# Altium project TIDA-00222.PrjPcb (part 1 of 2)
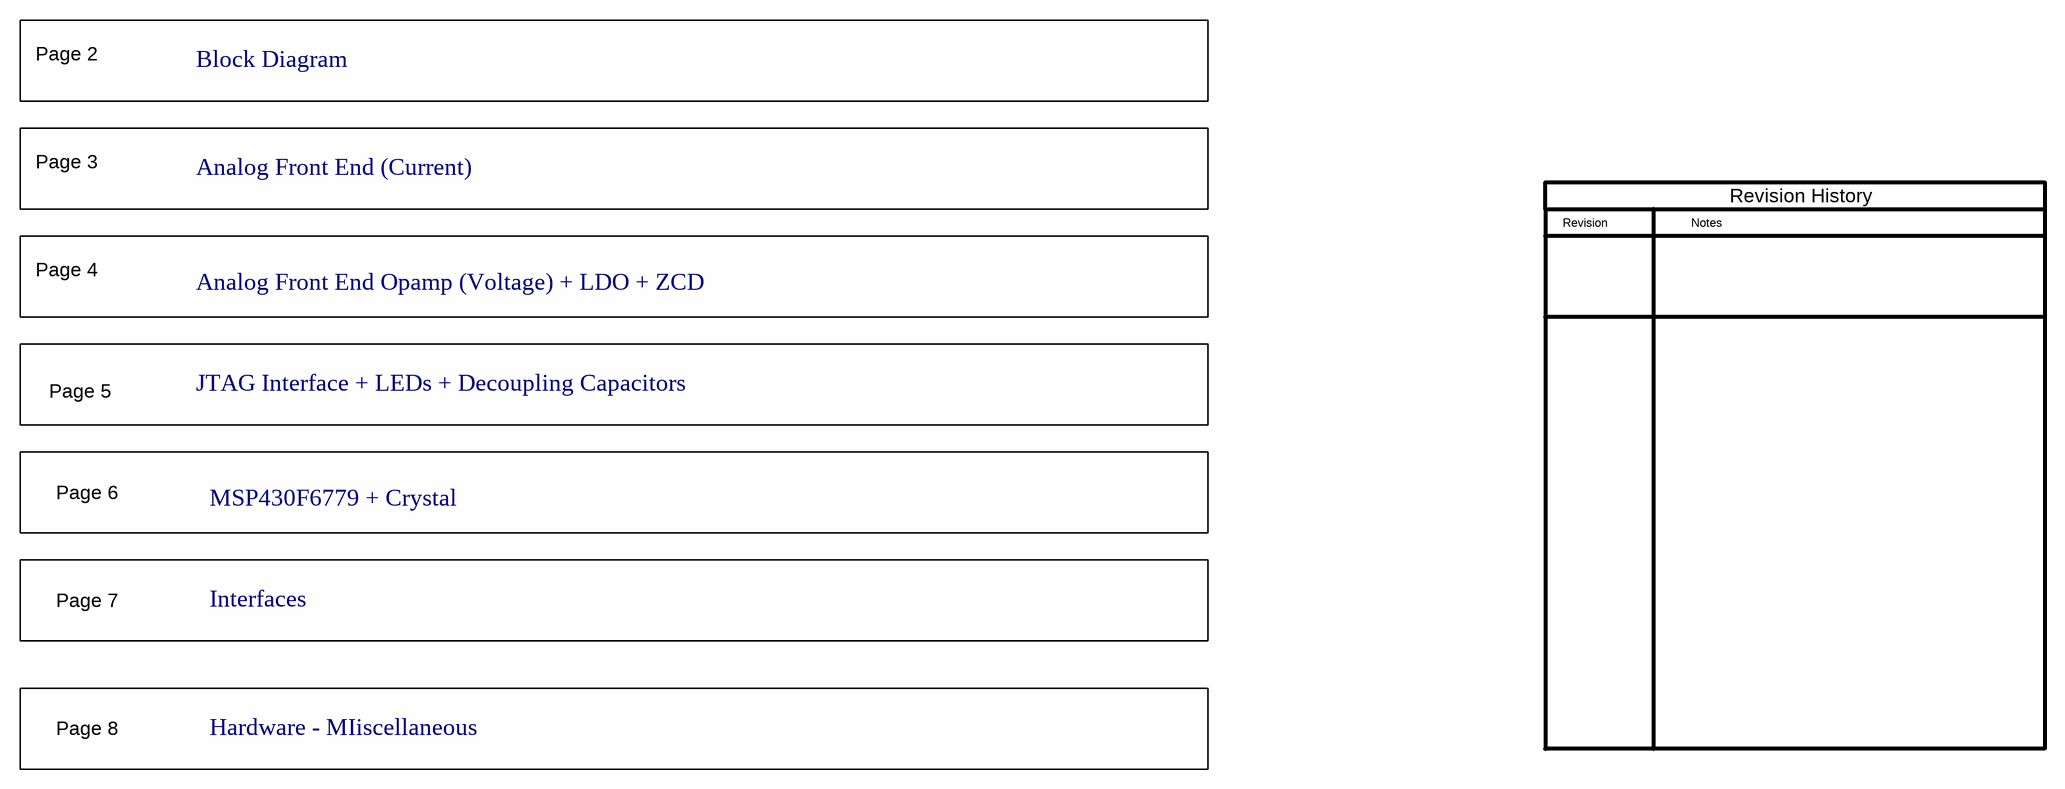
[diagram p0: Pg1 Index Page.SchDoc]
CopyrightYear: 2014; PCB_Rev: E1; PRJ_Customer: Public Release; PRJ_Engineer: Prahlad Supeda; PRJ_Number: TIDA-00222; PRJ_Title: TIDA-0022 - ISE3004; SCH_Rev: E1; TechSupport: http://www.ti.com/support
8 sheets, 217 parts. Net scope: flat (ports and power ports of the same name join across sheets).
Board file: TIDA-00222.PcbDoc
Sheets:
  Pg1 Index Page.SchDoc
  Pg2 Block Diagram.SchDoc
  Pg3.Analog Front End (Current).SchDoc
  Pg4.Analog Front End Opamp (Voltage) + LDO + ZCD.SchDoc
  Pg5.JTAG Interface + LEDs + Decoupling Capacitors.SchDoc
  Pg6.MSP430F6779 + Crystal.SchDoc
  Pg7.Interfaces.SchDoc
  Pg8.HARDWARE - MISCELLANEOUS.SchDoc

## Sheet Pg1 Index Page.SchDoc: Index Page
size 431 x 279 mm; Date: Not shown in title block; ApprovedBy: Not shown in title block; CheckedBy: Not shown in title block; Author: Not shown in title block; CompanyName: Not shown in title block; Engineer: Not shown in title block; Organization: Not shown in title block; Address1: Not shown in title block; Address2: Not shown in title block; Address3: Not shown in title block; Address4: Not shown in title block; DocumentNumber: 1; Revision: Use project parameter SCH_Rev; SheetNumber: 1; SheetTotal: 8; PageSetup: Record=PageOptions|CenterHorizontal=True|CenterVertical=True|PrintScale=1.00|XCorrection=1.00|YCorrection=1.00|PrintKind=0|BorderSize=5000000|LeftOffset=0|BottomOffset=0|Orientation=2|PaperLength=1000|PaperWidth=1000|Scale=100|PaperSource=15|PrintQuality=600|MediaType=1|DitherType=10|PaperKind=Letter|PrintScaleMode=1

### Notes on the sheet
- Page 2
- Block Diagram
- Page 3
- Analog Front End (Current)
- Revision
- Notes
- Revision History
- Page 4
- Analog Front End Opamp (Voltage) + LDO + ZCD
- Page 5
- JTAG Interface + LEDs + Decoupling Capacitors
- Page 6
- MSP430F6779 + Crystal
- Page 7
- Interfaces
- Page 8
- Hardware - MIiscellaneous

## Sheet Pg2 Block Diagram.SchDoc: Block Diagram
size 431 x 279 mm; Date: Not shown in title block; ApprovedBy: Not shown in title block; CheckedBy: Not shown in title block; Author: Not shown in title block; CompanyName: Not shown in title block; Engineer: Not shown in title block; Organization: Not shown in title block; Address1: Not shown in title block; Address2: Not shown in title block; Address3: Not shown in title block; Address4: Not shown in title block; DocumentNumber: 2; Revision: Use project parameter SCH_Rev; SheetNumber: 2; SheetTotal: 8; PageSetup: Record=PageOptions|CenterHorizontal=True|CenterVertical=True|PrintScale=1.00|XCorrection=1.00|YCorrection=1.00|PrintKind=0|BorderSize=5000000|LeftOffset=0|BottomOffset=0|Orientation=2|PaperLength=1000|PaperWidth=1000|Scale=100|PaperSource=15|PrintQuality=600|MediaType=1|DitherType=10|PaperKind=Letter|PrintScaleMode=1
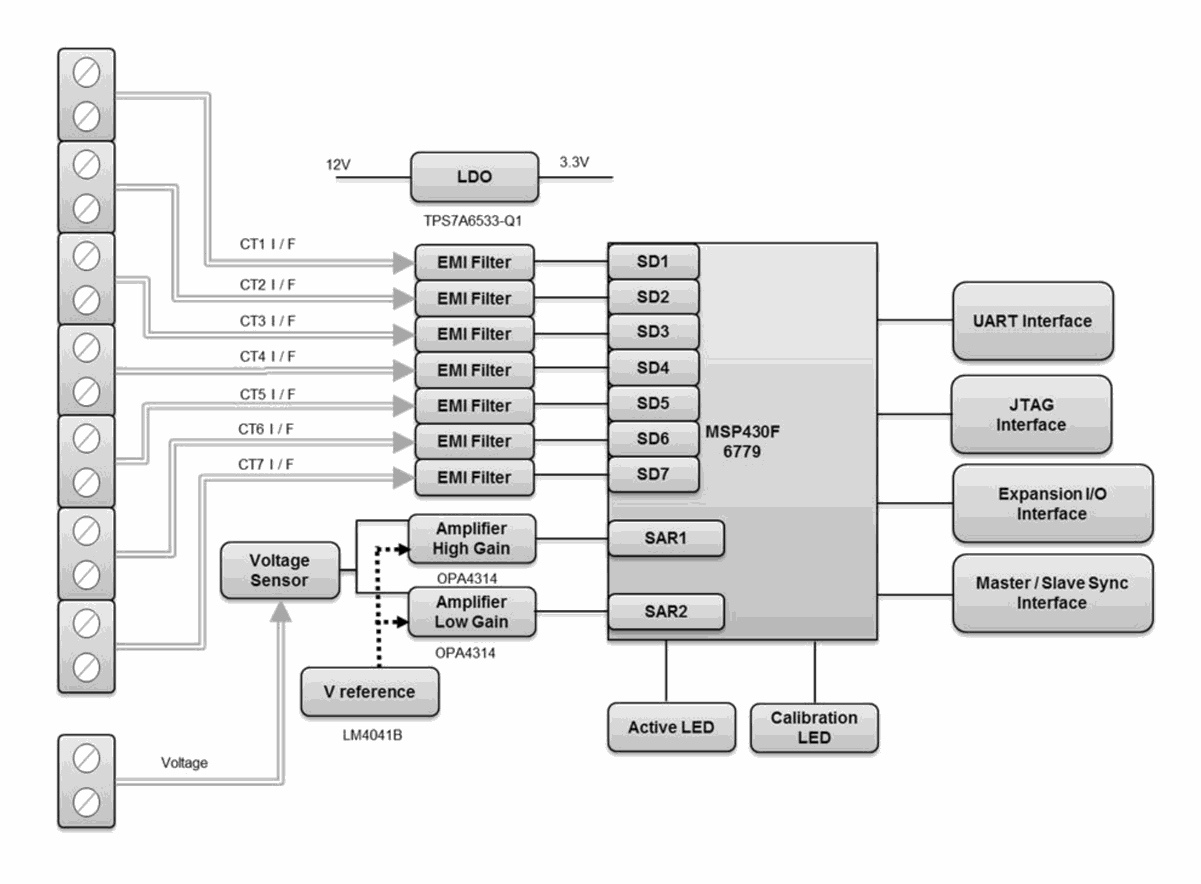
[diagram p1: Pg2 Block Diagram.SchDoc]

## Sheet Pg3.Analog Front End (Current).SchDoc: Analog Front End (Current)
size 431 x 279 mm; Date: Not shown in title block; ApprovedBy: Not shown in title block; CheckedBy: Not shown in title block; Author: Not shown in title block; CompanyName: Not shown in title block; Engineer: Not shown in title block; Organization: Not shown in title block; Address1: Not shown in title block; Address2: Not shown in title block; Address3: Not shown in title block; Address4: Not shown in title block; DocumentNumber: 3; Revision: Use project parameter SCH_Rev; SheetNumber: 3; SheetTotal: 8; PageSetup: Record=PageOptions|CenterHorizontal=True|CenterVertical=True|PrintScale=1.00|XCorrection=1.00|YCorrection=1.00|PrintKind=0|BorderSize=5000000|LeftOffset=0|BottomOffset=0|Orientation=2|PaperLength=1000|PaperWidth=1000|Scale=100|PaperSource=15|PrintQuality=600|MediaType=1|DitherType=10|PaperKind=Letter|PrintScaleMode=1
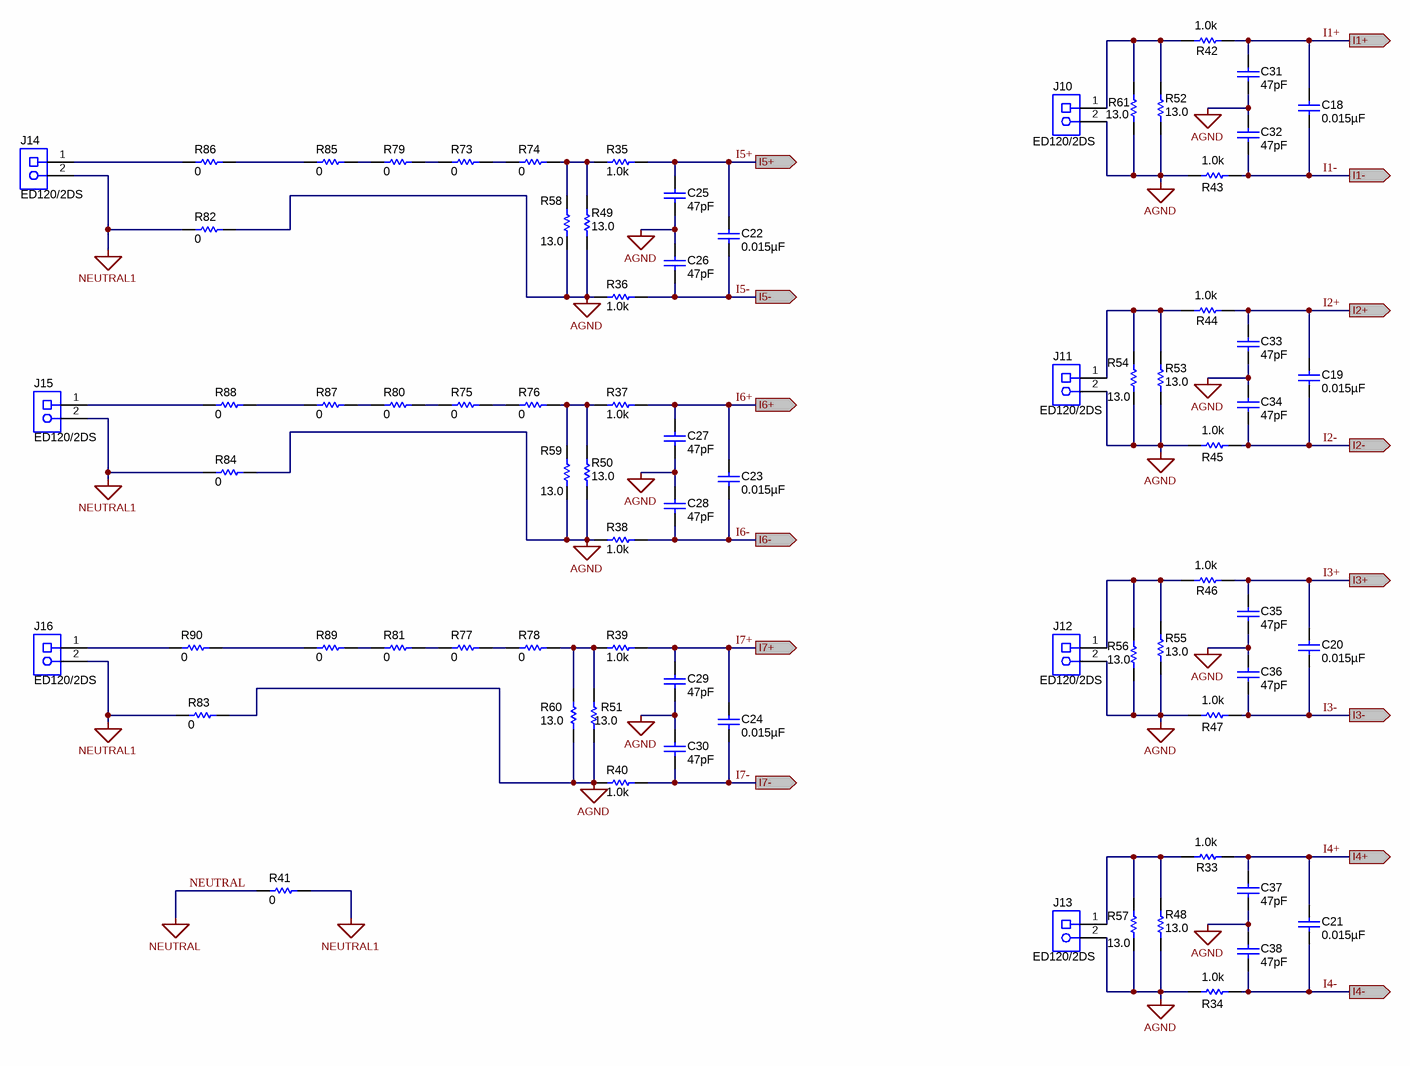
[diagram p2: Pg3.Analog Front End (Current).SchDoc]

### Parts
C18  ValueDisplayed: 0.015µF  [0805_HV]  (hidden comment: 08055C153KAT2A)
C19  ValueDisplayed: 0.015µF  [0805_HV]  (hidden comment: 08055C153KAT2A)
C20  ValueDisplayed: 0.015µF  [0805_HV]  (hidden comment: 08055C153KAT2A)
C21  ValueDisplayed: 0.015µF  [0805_HV]  (hidden comment: 08055C153KAT2A)
C22  ValueDisplayed: 0.015µF  [0805_HV]  (hidden comment: 08055C153KAT2A)
C23  ValueDisplayed: 0.015µF  [0805_HV]  (hidden comment: 08055C153KAT2A)
C24  ValueDisplayed: 0.015µF  [0805_HV]  (hidden comment: 08055C153KAT2A)
C25  ValueDisplayed: 47pF  [0805_HV]  (hidden comment: GRM21A5C2E470JW01D)
C26  ValueDisplayed: 47pF  [0805_HV]  (hidden comment: GRM21A5C2E470JW01D)
C27  ValueDisplayed: 47pF  [0805_HV]  (hidden comment: GRM21A5C2E470JW01D)
C28  ValueDisplayed: 47pF  [0805_HV]  (hidden comment: GRM21A5C2E470JW01D)
C29  ValueDisplayed: 47pF  [0805_HV]  (hidden comment: GRM21A5C2E470JW01D)
C30  ValueDisplayed: 47pF  [0805_HV]  (hidden comment: GRM21A5C2E470JW01D)
C31  ValueDisplayed: 47pF  [0805_HV]  (hidden comment: GRM21A5C2E470JW01D)
C32  ValueDisplayed: 47pF  [0805_HV]  (hidden comment: GRM21A5C2E470JW01D)
C33  ValueDisplayed: 47pF  [0805_HV]  (hidden comment: GRM21A5C2E470JW01D)
C34  ValueDisplayed: 47pF  [0805_HV]  (hidden comment: GRM21A5C2E470JW01D)
C35  ValueDisplayed: 47pF  [0805_HV]  (hidden comment: GRM21A5C2E470JW01D)
C36  ValueDisplayed: 47pF  [0805_HV]  (hidden comment: GRM21A5C2E470JW01D)
C37  ValueDisplayed: 47pF  [0805_HV]  (hidden comment: GRM21A5C2E470JW01D)
C38  ValueDisplayed: 47pF  [0805_HV]  (hidden comment: GRM21A5C2E470JW01D)
J10  ED120/2DS  [CONN_ED120-2DS]
J11  ED120/2DS  [CONN_ED120-2DS]
J12  ED120/2DS  [CONN_ED120-2DS]
J13  ED120/2DS  [CONN_ED120-2DS]
J14  ED120/2DS  [CONN_ED120-2DS]
J15  ED120/2DS  [CONN_ED120-2DS]
J16  ED120/2DS  [CONN_ED120-2DS]
R33  value 1.0k  [0603]  (hidden comment: CRCW06031K00JNEA)
R34  value 1.0k  [0603]  (hidden comment: CRCW06031K00JNEA)
R35  value 1.0k  [0603]  (hidden comment: CRCW06031K00JNEA)
R36  value 1.0k  [0603]  (hidden comment: CRCW06031K00JNEA)
R37  value 1.0k  [0603]  (hidden comment: CRCW06031K00JNEA)
R38  value 1.0k  [0603]  (hidden comment: CRCW06031K00JNEA)
R39  value 1.0k  [0603]  (hidden comment: CRCW06031K00JNEA)
R40  value 1.0k  [0603]  (hidden comment: CRCW06031K00JNEA)
R41  value 0  [0805_HV]  (hidden comment: CRCW08050000Z0EA)
R42  value 1.0k  [0603]  (hidden comment: CRCW06031K00JNEA)
R43  value 1.0k  [0603]  (hidden comment: CRCW06031K00JNEA)
R44  value 1.0k  [0603]  (hidden comment: CRCW06031K00JNEA)
R45  value 1.0k  [0603]  (hidden comment: CRCW06031K00JNEA)
R46  value 1.0k  [0603]  (hidden comment: CRCW06031K00JNEA)
R47  value 1.0k  [0603]  (hidden comment: CRCW06031K00JNEA)
R48  value 13.0  [0805_HV]  (hidden comment: CRCW080513R0FKEA)
R49  value 13.0  [0805_HV]  (hidden comment: CRCW080513R0FKEA)
R50  value 13.0  [0805_HV]  (hidden comment: CRCW080513R0FKEA)
R51  value 13.0  [0805_HV]  (hidden comment: CRCW080513R0FKEA)
R52  value 13.0  [0805_HV]  (hidden comment: CRCW080513R0FKEA)
R53  value 13.0  [0805_HV]  (hidden comment: CRCW080513R0FKEA)
R54  value 13.0  [0805_HV]  (hidden comment: CRCW080513R0FKEA)
R55  value 13.0  [0805_HV]  (hidden comment: CRCW080513R0FKEA)
R56  value 13.0  [0805_HV]  (hidden comment: CRCW080513R0FKEA)
R57  value 13.0  [0805_HV]  (hidden comment: CRCW080513R0FKEA)
R58  value 13.0  [0805_HV]  (hidden comment: CRCW080513R0FKEA)
R59  value 13.0  [0805_HV]  (hidden comment: CRCW080513R0FKEA)
R60  value 13.0  [0805_HV]  (hidden comment: CRCW080513R0FKEA)
R61  value 13.0  [0805_HV]  (hidden comment: CRCW080513R0FKEA)
R73  value 0  [0805_HV]  (hidden comment: CRCW08050000Z0EA)
R74  value 0  [0805_HV]  (hidden comment: CRCW08050000Z0EA)
R75  value 0  [0805_HV]  (hidden comment: CRCW08050000Z0EA)
R76  value 0  [0805_HV]  (hidden comment: CRCW08050000Z0EA)
R77  value 0  [0805_HV]  (hidden comment: CRCW08050000Z0EA)
R78  value 0  [0805_HV]  (hidden comment: CRCW08050000Z0EA)
R79  value 0  [0805_HV]  (hidden comment: CRCW08050000Z0EA)
R80  value 0  [0805_HV]  (hidden comment: CRCW08050000Z0EA)
R81  value 0  [0805_HV]  (hidden comment: CRCW08050000Z0EA)
R82  value 0  [0805_HV]  (hidden comment: CRCW08050000Z0EA)
R83  value 0  [0805_HV]  (hidden comment: CRCW08050000Z0EA)
R84  value 0  [0805_HV]  (hidden comment: CRCW08050000Z0EA)
R85  value 0  [0805_HV]  (hidden comment: CRCW08050000Z0EA)
R86  value 0  [0805_HV]  (hidden comment: CRCW08050000Z0EA)
R87  value 0  [0805_HV]  (hidden comment: CRCW08050000Z0EA)
R88  value 0  [0805_HV]  (hidden comment: CRCW08050000Z0EA)
R89  value 0  [0805_HV]  (hidden comment: CRCW08050000Z0EA)
R90  value 0  [0805_HV]  (hidden comment: CRCW08050000Z0EA)

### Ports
I1+ (out), I1- (out), I2+ (out), I2- (out), I3+ (out), I3- (out), I4+ (out), I4- (out), I5+ (out), I5- (out), I6+ (out), I6- (out), I7+ (out), I7- (out)

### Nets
AGND: C25.2 C26.1 C27.2 C28.1 C29.2 C30.1 C31.2 C32.1 C33.2 C34.1 C35.2 C36.1 C37.2 C38.1 J10.2 J11.2 J12.2 J13.2 R34.2 R36.2 R38.2 R40.2 R43.2 R45.2 R47.2 R48.1 R49.2 R50.2 R51.1 R52.1 R53.1 R54.1 R55.1 R56.1 R57.1 R58.1 R59.1 R60.2 R61.1 R82.2 R83.2 R84.2
NEUTRAL: R41.1
NEUTRAL1: J14.2 J15.2 J16.2 R41.2 R82.1 R83.1 R84.1
I1+: C18.1 C31.1 R42.1 ; port I1+
I1-: C18.2 C32.2 R43.1 ; port I1-
I2+: C19.1 C33.1 R44.1 ; port I2+
I2-: C19.2 C34.2 R45.1 ; port I2-
I3+: C20.1 C35.1 R46.1 ; port I3+
I3-: C20.2 C36.2 R47.1 ; port I3-
I4+: C21.1 C37.1 R33.1 ; port I4+
I4-: C21.2 C38.2 R34.1 ; port I4-
I5+: C22.1 C25.1 R35.1 ; port I5+
I5-: C22.2 C26.2 R36.1 ; port I5-
I6+: C23.1 C27.1 R37.1 ; port I6+
I6-: C23.2 C28.2 R38.1 ; port I6-
I7+: C24.1 C29.1 R39.1 ; port I7+
I7-: C24.2 C30.2 R40.1 ; port I7-
NetJ10_1: J10.1 R42.2 R52.2 R61.2
NetJ11_1: J11.1 R44.2 R53.2 R54.2
NetJ12_1: J12.1 R46.2 R55.2 R56.2
NetJ13_1: J13.1 R33.2 R48.2 R57.2
NetJ14_1: J14.1 R86.1
NetJ15_1: J15.1 R88.1
NetJ16_1: J16.1 R90.1
NetR35_2: R35.2 R49.1 R58.2 R74.2
NetR37_2: R37.2 R50.1 R59.2 R76.2
NetR39_2: R39.2 R51.2 R60.1 R78.2
NetR73_1: R73.1 R79.2
NetR73_2: R73.2 R74.1
NetR75_1: R75.1 R80.2
NetR75_2: R75.2 R76.1
NetR77_1: R77.1 R81.2
NetR77_2: R77.2 R78.1
NetR79_1: R79.1 R85.2
NetR80_1: R80.1 R87.2
NetR81_1: R81.1 R89.2
NetR85_1: R85.1 R86.2
NetR87_1: R87.1 R88.2
NetR89_1: R89.1 R90.2

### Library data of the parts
C18-C24 = 08055C153KAT2A: CAP, CERM, 0.015uF, 50V, +/-10%, X7R, 0805; Manufacturer: AVX; Polarized: N; CompType: Capacitor; U/M: EA; Cap_F: 0.000000015; Tolerance_%: 10; ESR_Ohm: 0.063; Value1: 0.063 ohm; VDC_V: 50; TaMin_C: -55; TaMax_C: 125; Cap_Case: 0805
C25-C38 = GRM21A5C2E470JW01D: CAP, CERM, 47pF, 500V, +/-5%, C0G/NP0, 0805; Manufacturer: MuRata; Polarized: N; CompType: Capacitor; U/M: EA; Cap_F: 0.000000000047; Tolerance_%: 5; Value1: Unknown; VDC_V: 250; Value2: 250V; TaMin_C: -55; TaMax_C: 125; Cap_Case: 0805
J10-J16 = ED120/2DS: TERMINAL BLOCK 5.08MM VERT 2POS, TH; Manufacturer: On-Shore Technology; SymbolCreator: a0412235; U/M: EA
R33-R40 R42-R47 = RC0603JR-071KL: RES, 1.0k ohm, 5%, 0.1W, 0603; Manufacturer: Vishay-Dale; CompType: Resistor; Res_ohm: 1000; Value_Code: 1k00; Tolerance_%: 5; Power_W: 0.1; VDC_V: 50; TempCo: 100 ppm/C; EIA_Code: E24; U/M: EA
R41 R73-R90 = CRCW0805330KJNEA: RES, 0 ohm, 5%, 0.125W, 0805; Manufacturer: Vishay-Dale; CompType: Resistor; Tolerance_%: 5; Power_W: 0.125; VDC_V: 150; TempCo: 200 ppm/C; EIA_Code: E24; U/M: EA
R48-R61 = CRCW080513R0FKEA: RES, 13.0 ohm, 1%, 0.125W, 0805; Manufacturer: Vishay-Dale; CompType: Resistor; Res_ohm: 13; Value_Code: 13R0; Tolerance_%: 1; Power_W: 0.125; VDC_V: 150; TempCo: 100 ppm/C; EIA_Code: E96; U/M: EA

## Sheet Pg4.Analog Front End Opamp (Voltage) + LDO + ZCD.SchDoc: Analog Front End Opamp (Voltage) + LDO + ZCD
size 431 x 279 mm; Date: Not shown in title block; ApprovedBy: Not shown in title block; CheckedBy: Not shown in title block; Author: Not shown in title block; CompanyName: Not shown in title block; Engineer: Not shown in title block; Organization: Not shown in title block; Address1: Not shown in title block; Address2: Not shown in title block; Address3: Not shown in title block; Address4: Not shown in title block; DocumentNumber: 4; Revision: Use project parameter SCH_Rev; SheetNumber: 4; SheetTotal: 8; PageSetup: Record=PageOptions|CenterHorizontal=True|CenterVertical=True|PrintScale=1.00|XCorrection=1.00|YCorrection=1.00|PrintKind=0|BorderSize=5000000|LeftOffset=0|BottomOffset=0|Orientation=2|PaperLength=1000|PaperWidth=1000|Scale=100|PaperSource=15|PrintQuality=600|MediaType=1|DitherType=10|PaperKind=Letter|PrintScaleMode=1
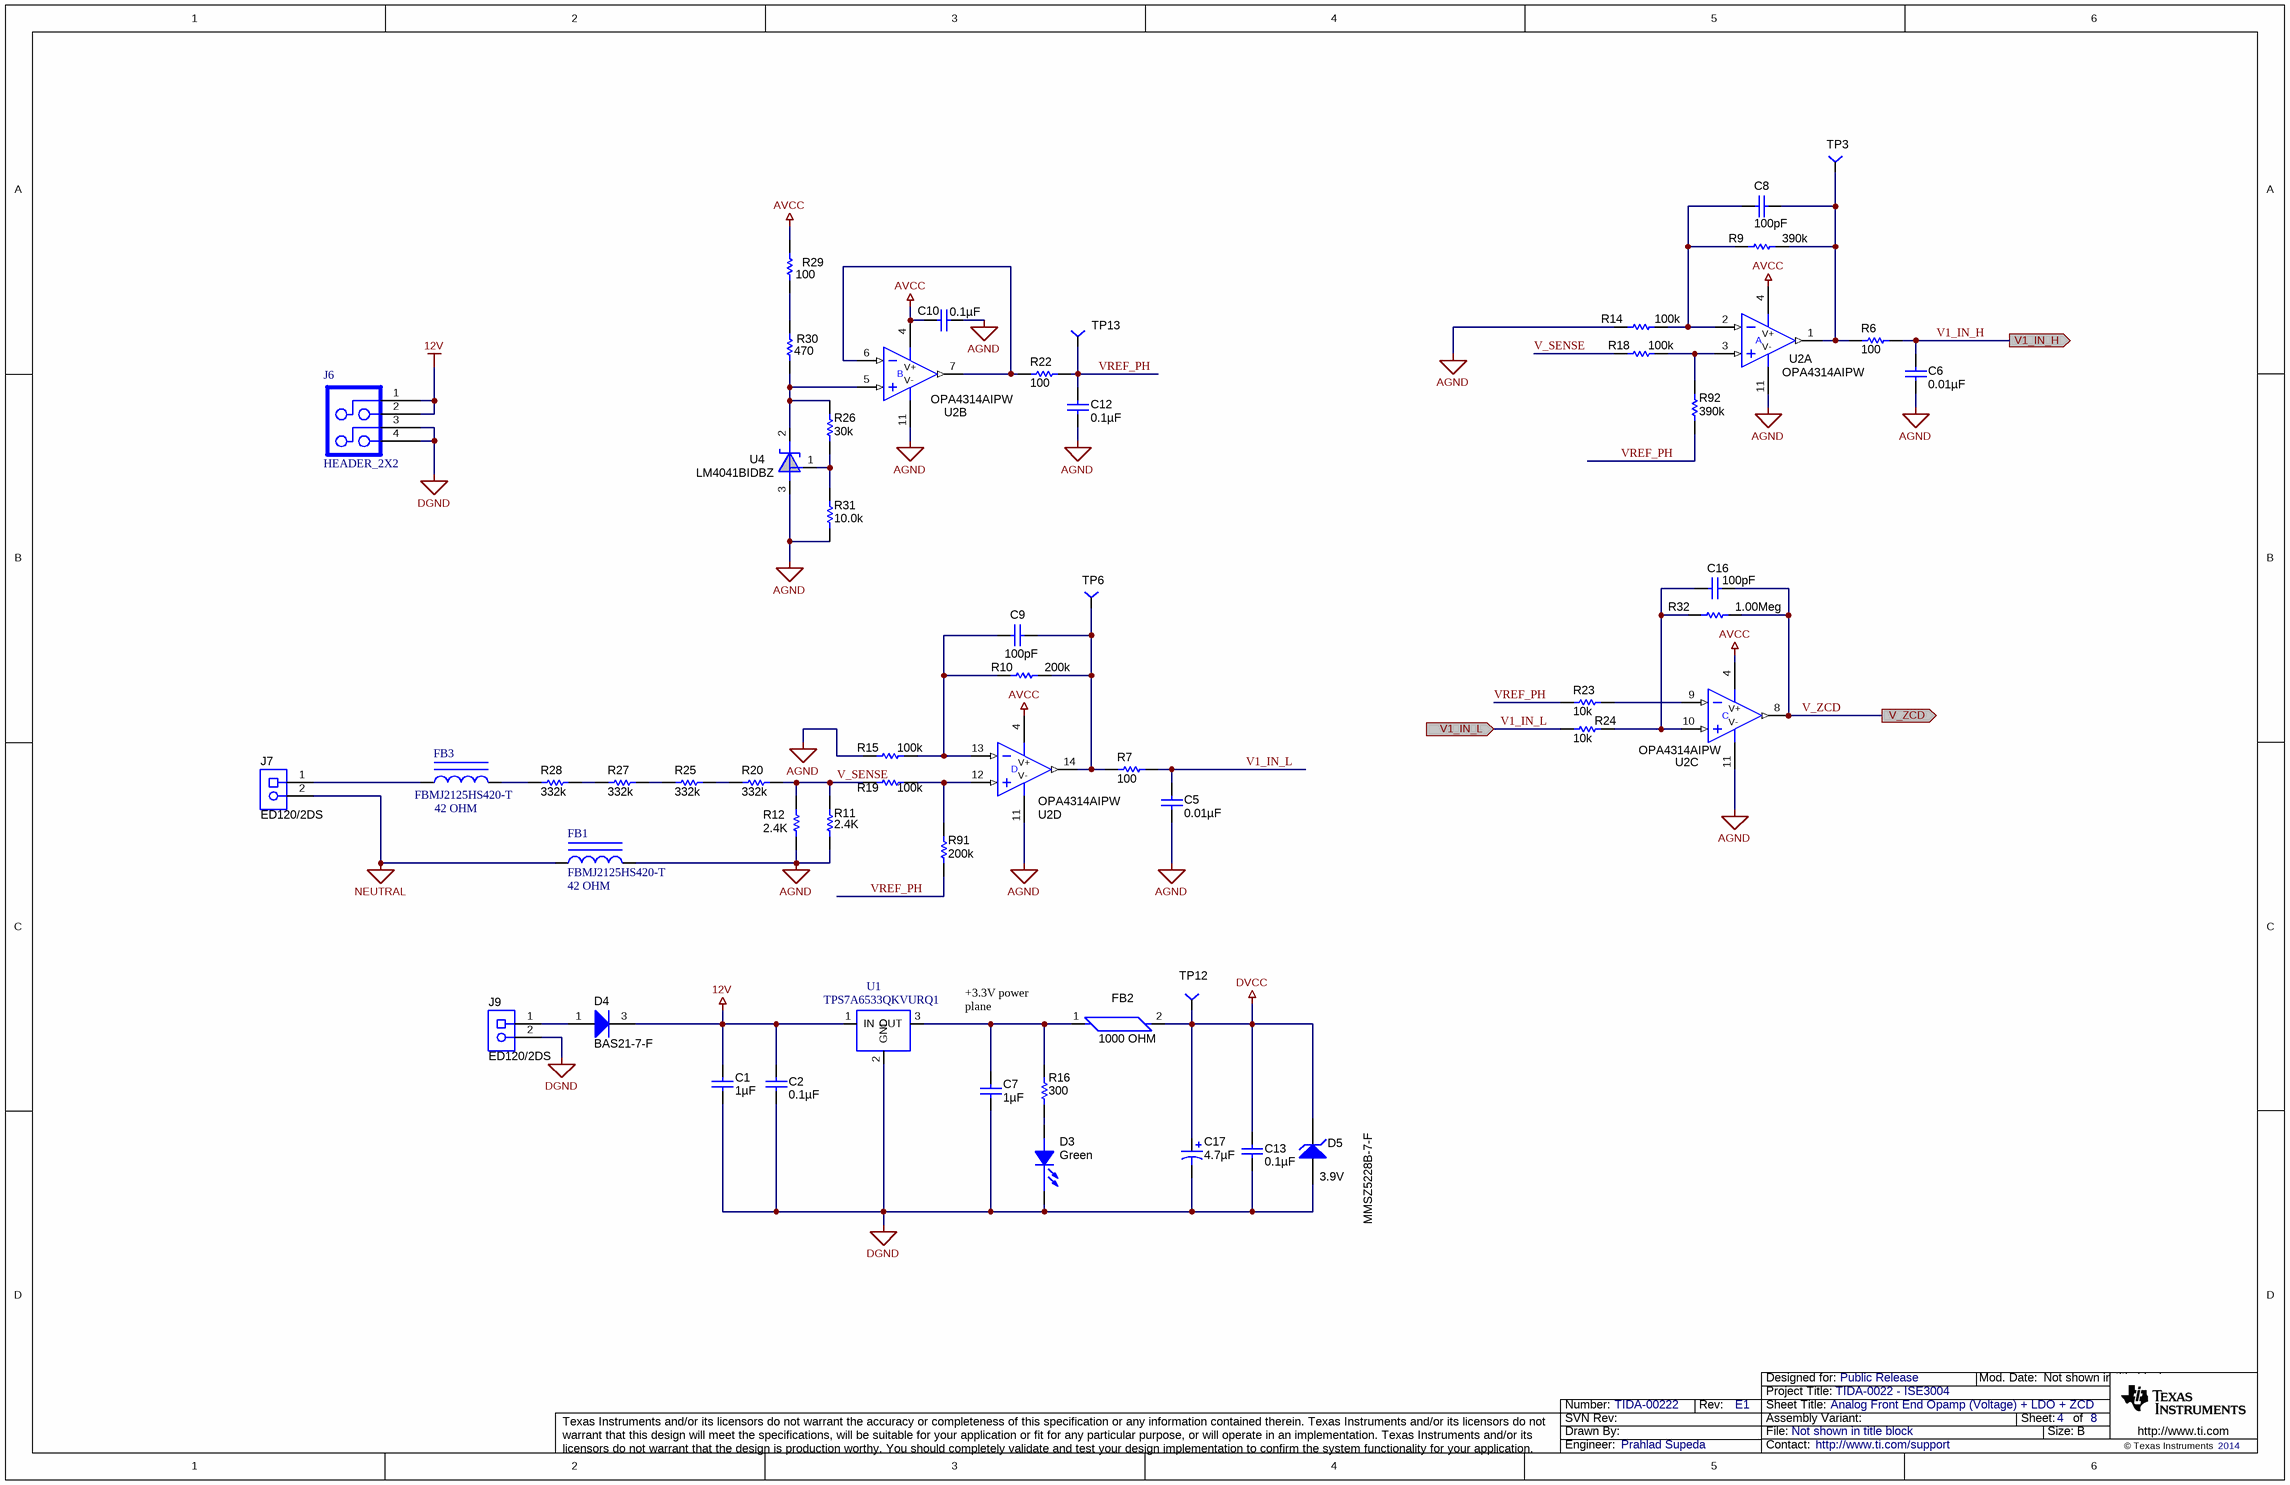
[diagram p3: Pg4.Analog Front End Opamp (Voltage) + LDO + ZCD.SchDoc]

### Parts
C1  ValueDisplayed: 1µF  [0603]  (hidden comment: C1608X7R1C105K)
C2  ValueDisplayed: 0.1µF  [0603]  (hidden comment: C0603C104K5RACTU)
C5  ValueDisplayed: 0.01µF  [0603]  (hidden comment: C1608C0G1E103J)
C6  ValueDisplayed: 0.01µF  [0603]  (hidden comment: C1608C0G1E103J)
C7  ValueDisplayed: 1µF  [0603]  (hidden comment: C1608X7R1C105K)
C8  ValueDisplayed: 100pF  [0603]  (hidden comment: 06035A101FAT2A)
C9  ValueDisplayed: 100pF  [0603]  (hidden comment: 06035A101FAT2A)
C10  ValueDisplayed: 0.1µF  [0603]  (hidden comment: 06033C104JAT2A)
C12  ValueDisplayed: 0.1µF  [0603]  (hidden comment: 06033C104JAT2A)
C13  ValueDisplayed: 0.1µF  [0603]  (hidden comment: C0603C104K5RACTU)
C16  ValueDisplayed: 100pF  [0603]  (hidden comment: 06035A101FAT2A)
C17  ValueDisplayed: 4.7µF  [6032-28]  (hidden comment: 293D475X9035C2TE3)
D3  value Green  [LED0603AA]  (hidden comment: LED_LG L29K-G2J1-24-Z)
D4  BAS21-7-F  [SOT-23]
D5  MMSZ5228B-7-F  value 3.9V  [sod-123]
FB1  FBMJ2125HS420-T  value 42 OHM  [0805_hv]
FB2  1000 OHM  [0603]
FB3  FBMJ2125HS420-T  value 42 OHM  [0805_hv]
J6  HEADER_2X2  [HDR_2X2]
J7  ED120/2DS  [CONN_ED120-2DS]
J9  ED120/2DS  [CONN_ED120-2DS]
R6  value 100  [0603]  (hidden comment: CRCW0603100RFKEA)
R7  value 100  [0603]  (hidden comment: CRCW0603100RFKEA)
R9  value 390k  [0603]  (hidden comment: CRCW0603390KFKEA)
R10  value 200k  [0603]  (hidden comment: CRCW0603200KFKEA)
R11  value 2.4K  [0805_hv]  (hidden comment: CRCW08052K40FKEA)
R12  value 2.4K  [0805_hv]  (hidden comment: CRCW08052K40FKEA)
R14  value 100k  [0603]  (hidden comment: CRCW0603100KFKEA)
R15  value 100k  [0603]  (hidden comment: CRCW0603100KFKEA)
R16  value 300  [0603]  (hidden comment: CRCW0603300RJNEA)
R18  value 100k  [0603]  (hidden comment: CRCW0603100KFKEA)
R19  value 100k  [0603]  (hidden comment: CRCW0603100KFKEA)
R20  value 332k  [0805_HV]  (hidden comment: CRCW0805332KFKEA)
R22  value 100  [0603]  (hidden comment: CRCW0603100RFKEA)
R23  value 10k  [0603]  (hidden comment: CRCW060310K0JNEA)
R24  value 10k  [0603]  (hidden comment: CRCW060310K0JNEA)
R25  value 332k  [0805_HV]  (hidden comment: CRCW0805332KFKEA)
R26  value 30k  [0603]  (hidden comment: CRCW060330K0JNEA)
R27  value 332k  [0805_HV]  (hidden comment: CRCW0805332KFKEA)
R28  value 332k  [0805_HV]  (hidden comment: CRCW0805332KFKEA)
R29  value 100  [0603]  (hidden comment: CRCW0603100RFKEA)
R30  value 470  [0603]  (hidden comment: CRCW0603470RJNEA)
R31  value 10.0k  [0603]  (hidden comment: CRCW060310K0FKEA)
R32  value 1.00Meg  [0603]  (hidden comment: CRCW06031M00FKEA)
R91  value 200k  [0603]  (hidden comment: CRCW0603200KFKEA)
R92  value 390k  [0603]  (hidden comment: CRCW0603390KFKEA)
TP3  TP-040_RND  [TP-040_RND]  (value not drawn)
TP6  TP-040_RND  [TP-040_RND]  (value not drawn)
TP12  TP-040_RND  [TP-040_RND]  (value not drawn)
TP13  TP-040_RND  [TP-040_RND]  (value not drawn)
U1  TPS7A6533QKVURQ1  [KVU_1]
U2  OPA4314AIPW  [PW0014A_N]  (parts A,B,C,D of 4)
U4  LM4041BIDBZ  [SOT-23]

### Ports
V1_IN_H, V1_IN_L, V_ZCD

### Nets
12V: C1.1 C2.1 D4.3(K) J6.1 J6.2 U1.1(IN)
AGND: C5.1 C6.1 C10.1 C12.1 FB1.2 R11.2 R12.2 R14.2 R15.2 R31.1 U2.11(V-) U4.3(A)
AVCC: C10.2 R29.1 U2.4(V+)
DGND: C1.2 C2.2 C7.2 C13.2 C17.2(-) D3.1(C) D5.2(A) J6.3 J6.4 J9.2 U1.2(GND)
DVCC: C13.1 C17.1(+) D5.1(K) FB2.2 TP12.1
NEUTRAL: FB1.1 J7.2
V1_IN_H: C6.2 R6.2 ; port V1_IN_H
V1_IN_L: C5.2 R7.2 R24.2 ; port V1_IN_L
V_SENSE: R11.1 R12.1 R18.2 R19.2 R20.1
V_ZCD: C16.1 R32.2 U2.8(OUT) ; port V_ZCD
VREF_PH: C12.2 R22.2 R23.2 R91.1 R92.2 TP13.1
NetC7_1: C7.1 FB2.1 R16.2 U1.3(OUT)
NetC8_1: C8.1 R6.1 R9.1 TP3.1 U2.1(OUT)
NetC8_2: C8.2 R9.2 R14.1 U2.2(IN-)
NetC9_1: C9.1 R7.1 R10.1 TP6.1 U2.14(OUT)
NetC9_2: C9.2 R10.2 R15.1 U2.13(IN-)
NetC16_2: C16.2 R24.1 R32.1 U2.10(IN+)
NetD3_2: D3.2(A) R16.1
NetD4_1: D4.1(A) J9.1
NetFB3_1: FB3.1 J7.1
NetFB3_2: FB3.2 R28.2
NetR18_1: R18.1 R92.1 U2.3(IN+)
NetR19_1: R19.1 R91.2 U2.12(IN+)
NetR20_2: R20.2 R25.1
NetR22_1: R22.1 U2.6(IN-) U2.7(OUT)
NetR23_1: R23.1 U2.9(IN-)
NetR25_2: R25.2 R27.1
NetR26_1: R26.1 R31.2 U4.1(FB)
NetR26_2: R26.2 R30.1 U2.5(IN+) U4.2(C)
NetR27_2: R27.2 R28.1
NetR29_2: R29.2 R30.2

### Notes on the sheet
- (near FB2) +3.3V power
  plane

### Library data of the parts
C1 C7 = C1608X7R1C105K: CAP, CERM, 1uF, 16V, +/-10%, X7R, 0603; Manufacturer: TDK; Polarized: N; CompType: Capacitor; U/M: EA; Cap_F: 0.000001; Tolerance_%: 10; ESR_Ohm: 0.0057; Value1: 0.0057 ohm; VDC_V: 16; TaMin_C: -55; TaMax_C: 125
C2 C13 = C0603C104K5RACTU: CAP, CERM, 0.1uF, 50V, +/-10%, X7R, 0603; Manufacturer: Kemet; Polarized: N; CompType: Capacitor; U/M: EA; Cap_F: 0.0000001; Tolerance_%: 10; Value1: Unknown; VDC_V: 50; TaMin_C: -55; TaMax_C: 125
C5 C6 = C1608C0G1E103J: CAP, CERM, 0.01uF, 25V, +/-5%, C0G/NP0, 0603; Manufacturer: TDK; Polarized: N; CompType: Capacitor; U/M: EA; Cap_F: 0.00000001; Tolerance_%: 5; Value1: Unknown; VDC_V: 25; TaMin_C: -55; TaMax_C: 125
C8 C9 C16 = 06035A101FAT2A: CAP, CERM, 100pF, 50V, +/-1%, C0G/NP0, 0603; Manufacturer: AVX; Polarized: N; CompType: Capacitor; U/M: EA; Cap_F: 0.0000000001; Tolerance_%: 1; Value1: Unknown; VDC_V: 50; TaMin_C: -55; TaMax_C: 125
C10 C12 = 06033C104JAT2A: CAP, CERM, 0.1uF, 25V, +/-5%, X7R, 0603; Manufacturer: AVX; Polarized: N; CompType: Capacitor; U/M: EA; Cap_F: 0.0000001; Tolerance_%: 5; ESR_Ohm: 0.05; Value1: 0.05 ohm; VDC_V: 25; TaMin_C: -55; TaMax_C: 125
C17 = 293D475X9035C2TE3: CAP, TA, 4.7uF, 35V, +/-10%, 1.9 ohm, SMD; Manufacturer: Vishay-Sprague; Polarized: Y; CompType: Capacitor; U/M: EA; Cap_F: 0.0000047; Tolerance_%: 10; Value1: 1.9 ohm; VDC_V: 35; ESR_Ohm: 1.9; IRMS_A: 0.24; TaMin_C: -55; TaMax_C: 125; Cap_Case: C
D3 = LED_LG L29K-G2J1-24-Z: LED SmartLED Green 570NM; Manufacturer: OSRAM; SymbolCreator: x0120606
D4 = BAS21-7-F: Diode, Switching, 200V, 0.2A, SOT-23; Manufacturer: Diodes Inc.; U/M: EA; Vf_V: 1.25; Value2: 1.25V; Io_A: 0.2; Vr_V: 200; TJmax_C: 150; RJC_CperW: 500
D5 = 1SMB5915BT3G: DIODE ZENER 3.9V 500MW SOD123; Manufacturer: Diodes Incorporated; U/M: EA; Power_W: 0.55; Vz_V: 3.9; Value1: 0.55W; RJA_CperW: 226
FB1 FB3 = FBMJ2125HS420-T: FERRITE BEAD, 42 OHM, 4 A, DCR0.008 OHM, SMT-0805; Manufacturer: TAIYO YUDEN; SymbolCreator: x0199378
FB2 = MMZ1608B102C: FERRITE CHIP 1000 OHM 300MA 0603; Manufacturer: TDK Corporation; CompType: Ferrite Bead
J6 = HEADER_2X2: Header, 2x2-pin, 100mil spacing; Manufacturer: FCI; PartNumber: 67997-404HLF; area: 40000; Value: PEC02DAAN
J7 J9 = ED120/2DS: as J10 on sheet Pg3.Analog Front End (Current)
R6 R7 R22 R29 = CRCW0603100RFKEA: RES, 100 ohm, 1%, 0.1W, 0603; Manufacturer: Vishay-Dale; CompType: Resistor; Value_Code: 100R; Tolerance_%: 1; Power_W: 0.1; VDC_V: 75; TempCo: 100 ppm/C; EIA_Code: E96; U/M: EA
R9 R92 = RC0603FR-0739KL: RES 390K OHM 1/10W 1% 0603 SMD; Manufacturer: Vishay Dale; CompType: Resistor; Tolerance_%: 1; Value2: 0.1W; TempCo: 100 ppm/C; U/M: EA
R10 R91 = CRCW0603200KFKEA: RES, 200k ohm, 1%, 0.1W, 0603; Manufacturer: Vishay-Dale; CompType: Resistor; Res_ohm: 200000; Tolerance_%: 1; Power_W: 0.1; VDC_V: 75; TempCo: 100 ppm/C; EIA_Code: E96; U/M: EA
R11 R12 = CRCW120610K0FKEA: RES 2.40K OHM 1/8W 1% 0805 SMD; Manufacturer: Vishay-Dale; CompType: Resistor; Tolerance_%: 1; Power_W: 0.125W; TempCo: 100 ppm/C; U/M: EA
R14 R15 R18 R19 = CRCW0603100KFKEA: RES, 100k ohm, 1%, 0.1W, 0603; Manufacturer: Vishay-Dale; CompType: Resistor; Res_ohm: 100000; Tolerance_%: 1; Power_W: 0.1; VDC_V: 75; TempCo: 100 ppm/C; EIA_Code: E96; U/M: EA
R16 = CRCW0603300RJNEA: RES, 300 ohm, 5%, 0.1W, 0603; Manufacturer: Vishay-Dale; CompType: Resistor; Value_Code: 300R; Tolerance_%: 5; Power_W: 0.1; VDC_V: 75; TempCo: 200 ppm/C; EIA_Code: E24; U/M: EA
R20 R25 R27 R28 = CRCW0805332KFKEA: RES, 332k ohm, 1%, 0.125W, 0805; Manufacturer: Vishay-Dale; CompType: Resistor; Res_ohm: 332000; Tolerance_%: 1; Power_W: 0.125; VDC_V: 150; TempCo: 100 ppm/C; EIA_Code: E96; U/M: EA
R23 R24 = RNCF0603TKY10K0: RES 10K OHM 1/10W 5% 0603 SMD; Manufacturer: Vishay-Dale; CompType: Resistor; Res_ohm: 10000; Value_Code: 10k0; Tolerance_%: 0.01; Value1: 0.01%; Power_W: 0.063; Value2: 0.063W; VDC_V: 50; TempCo: 5 ppm/C; U/M: EA
R26 = CRCW060330K0JNEA: RES, 30k ohm, 5%, 0.1W, 0603; Manufacturer: Vishay-Dale; CompType: Resistor; Res_ohm: 30000; Value_Code: 30k0; Tolerance_%: 5; Power_W: 0.1; VDC_V: 75; TempCo: 200 ppm/C; EIA_Code: E24; U/M: EA
R30 = CRCW0603470RJNEA: RES, 470 ohm, 5%, 0.1W, 0603; Manufacturer: Vishay-Dale; CompType: Resistor; Value_Code: 470R; Tolerance_%: 5; Power_W: 0.1; VDC_V: 75; TempCo: 200 ppm/C; EIA_Code: E24; U/M: EA
R31 = CRCW060310K0FKEA: RES, 10.0k ohm, 1%, 0.1W, 0603; Manufacturer: Vishay-Dale; CompType: Resistor; Res_ohm: 10000; Value_Code: 10k0; Tolerance_%: 1; Power_W: 0.1; VDC_V: 75; TempCo: 100 ppm/C; EIA_Code: E96; U/M: EA
R32 = CRCW06031M00FKEA: RES 1.00M OHM 1/10W 1% 0603 SMD; Manufacturer: Vishay-Dale; CompType: Resistor; Res_ohm: 1000000; Value_Code: 1M00; Tolerance_%: 1; Power_W: 0.1; Value2: 0.1W; VDC_V: 75; TempCo: 100 ppm/C; EIA_Code: E96; U/M: EA
TP3 TP6 TP12 TP13 = TP-040_RND: Test Point, O.040 Hole; Manufacturer: STD; Value: STD
U1 = TPS7A6533QKVURQ1: IC, 300-mA 40-V LOW-DROPOUT REGULATOR WITH 25-uA QUIESCENT CURRENT; Manufacturer: TI; Alternate Manufacturer: None; Area: 136210
U2 = LMV324IPW: LOW-VOLTAGE RAIL-TO-RAIL OUTPUT OPERATIONAL AMPLIFIERS, PW0014A; Alternate Manufacturer: None; Manufacturer: Texas Instruments; SymbolCreator: a0411947; CompType: IC; U/M: EA
U4 = LM4041BIDBZ: IC, Micropower Shunt Voltage Reference 100 ppm/°C, 45µA-12mA,  Adjustable; Manufacturer: TI; Alternate Manufacturer: None; Area: 25500

## Sheet Pg5.JTAG Interface + LEDs + Decoupling Capacitors.SchDoc: JTAG Interface + LEDs + Decoupling Capacitors
size 431 x 279 mm; Date: Not shown in title block; ApprovedBy: Not shown in title block; CheckedBy: Not shown in title block; Author: Not shown in title block; CompanyName: Not shown in title block; Engineer: Not shown in title block; Organization: Not shown in title block; Address1: Not shown in title block; Address2: Not shown in title block; Address3: Not shown in title block; Address4: Not shown in title block; DocumentNumber: 5; Revision: Use project parameter SCH_Rev; SheetNumber: 5; SheetTotal: 8; PageSetup: Record=PageOptions|CenterHorizontal=True|CenterVertical=True|PrintScale=1.00|XCorrection=1.00|YCorrection=1.00|PrintKind=0|BorderSize=5000000|LeftOffset=0|BottomOffset=0|Orientation=2|PaperLength=1000|PaperWidth=1000|Scale=100|PaperSource=15|PrintQuality=600|MediaType=1|DitherType=10|PaperKind=Letter|PrintScaleMode=1
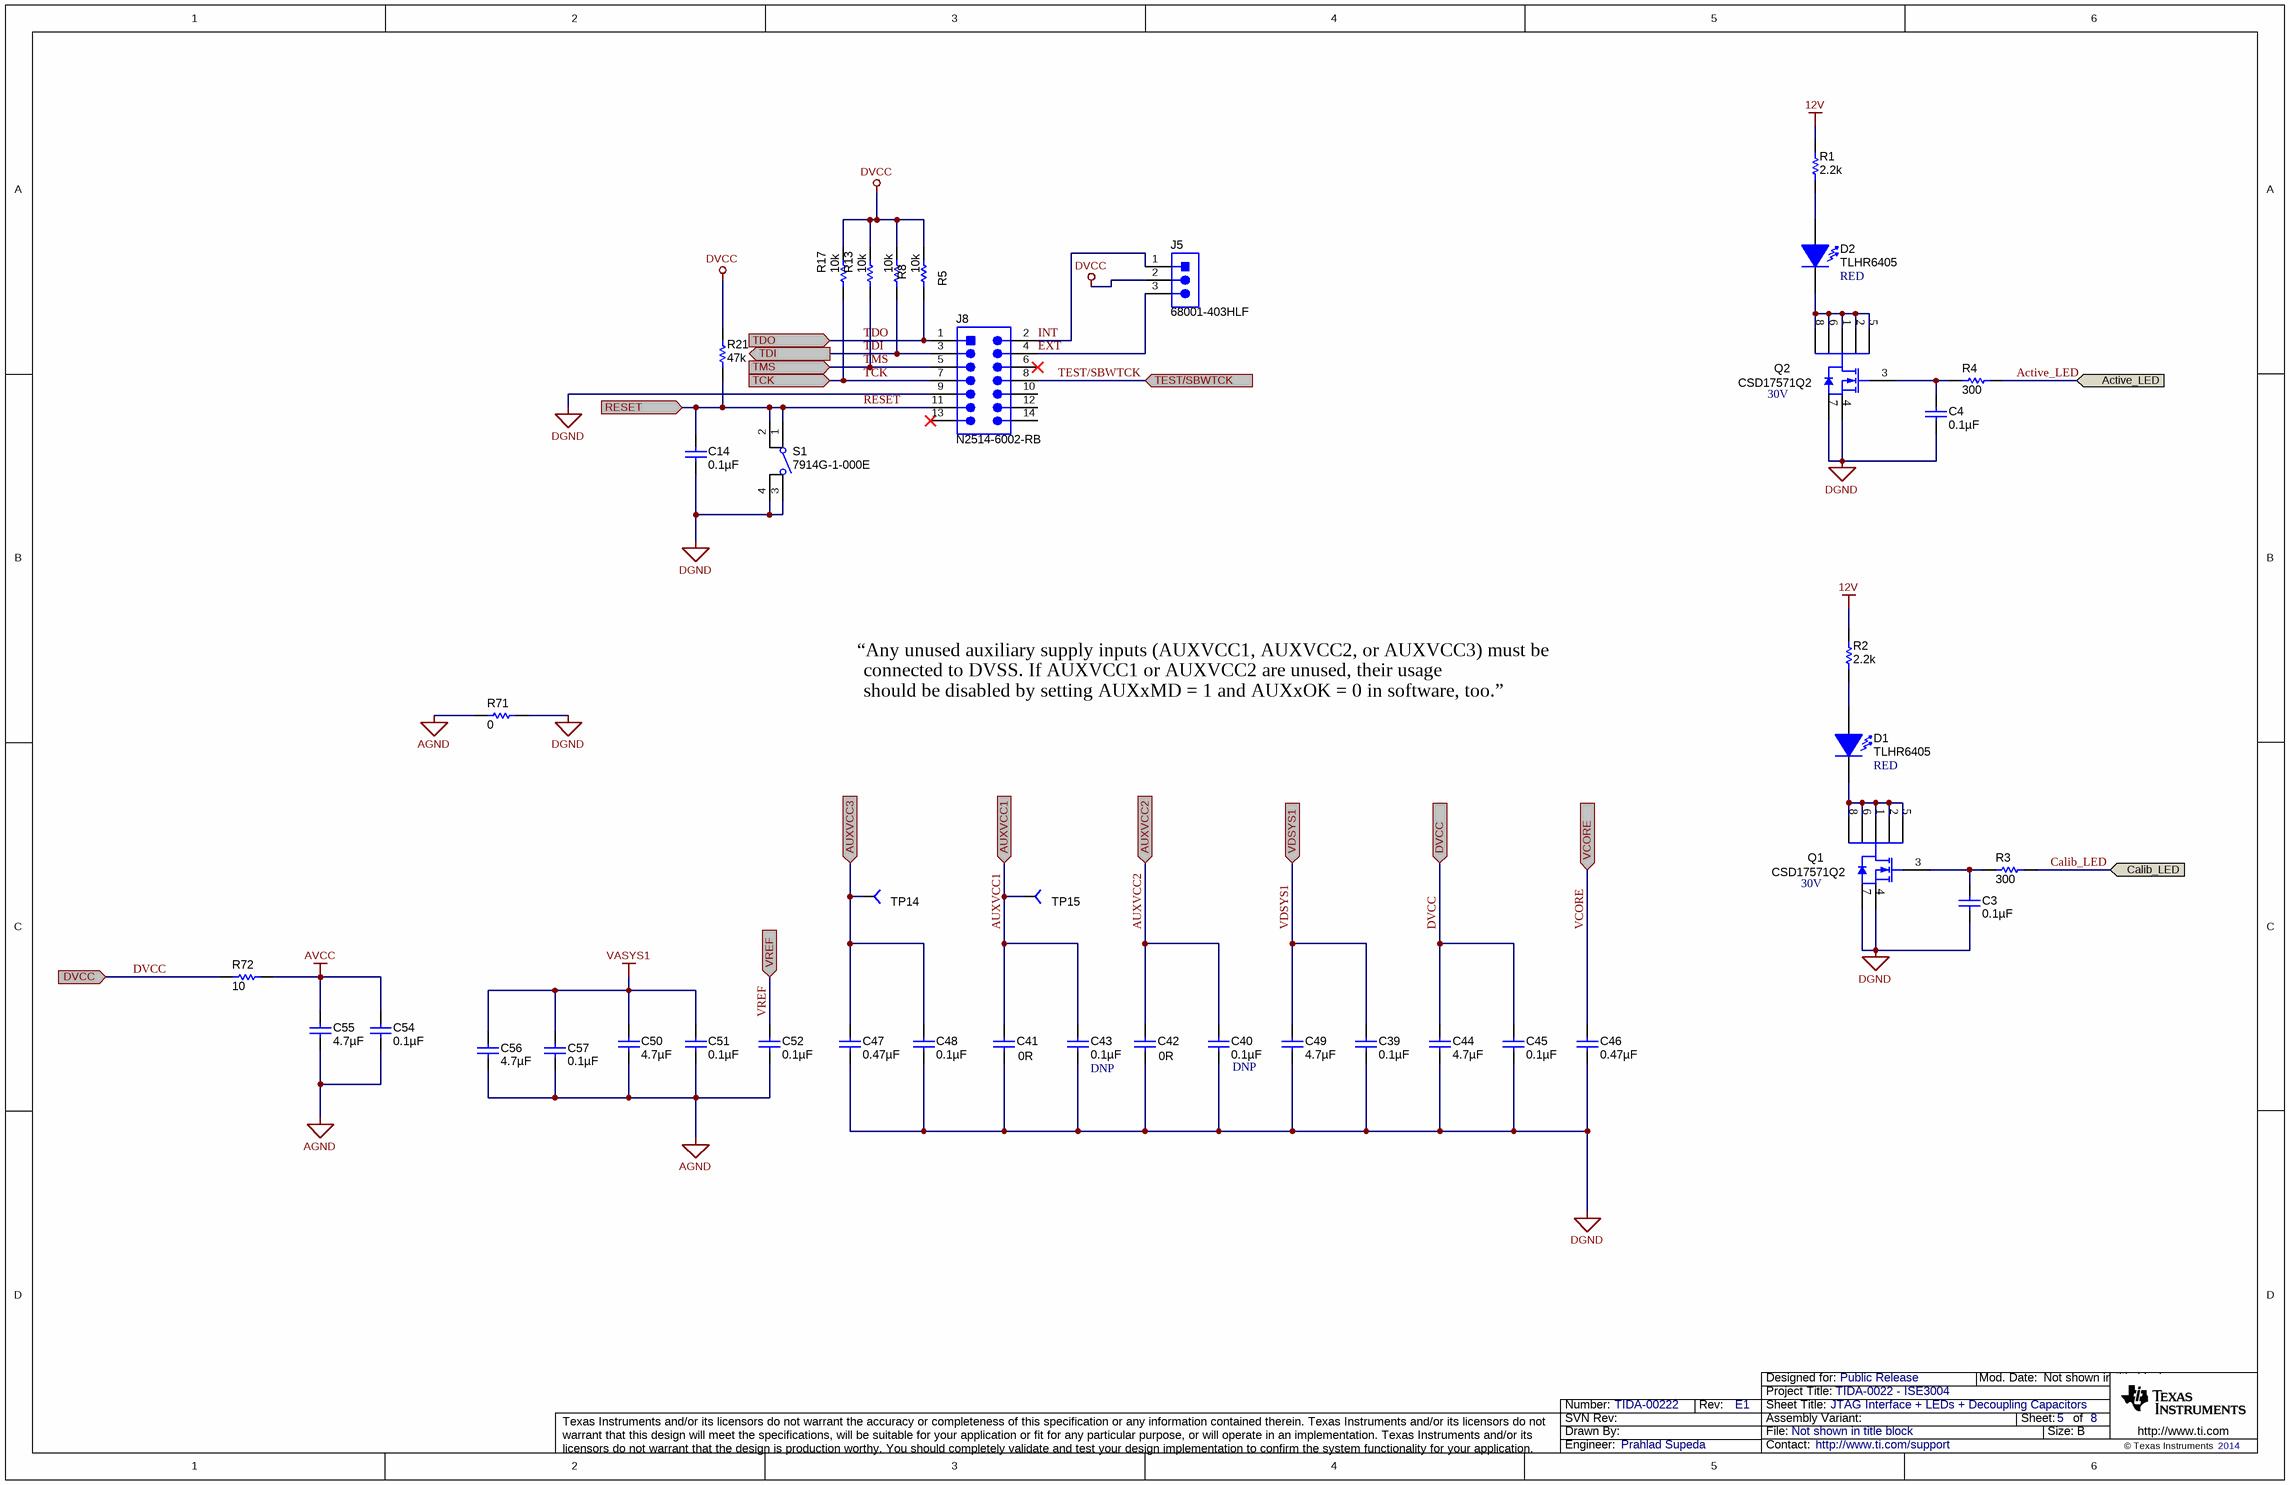
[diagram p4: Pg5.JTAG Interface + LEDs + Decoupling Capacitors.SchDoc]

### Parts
C3  ValueDisplayed: 0.1µF  [0603]  (hidden comment: 06033C104JAT2A)
C4  ValueDisplayed: 0.1µF  [0603]  (hidden comment: 06033C104JAT2A)
C14  ValueDisplayed: 0.1µF  [0603]  (hidden comment: 06033C104JAT2A)
C39  ValueDisplayed: 0.1µF  [0603]  (hidden comment: 06033C104JAT2A)
C40  ValueDisplayed: 0.1µF  Fitted: DNP  [0603]  (hidden comment: 06033C104JAT2A)
C41  value 0R  [0603]  (hidden comment: CRCW06030000Z0EA)
C42  value 0R  [0603]  (hidden comment: CRCW06030000Z0EA)
C43  ValueDisplayed: 0.1µF  Fitted: DNP  [0603]  (hidden comment: 06033C104JAT2A)
C44  ValueDisplayed: 4.7µF  [0603]  (hidden comment: 0603ZD475KAT2A)
C45  ValueDisplayed: 0.1µF  [0603]  (hidden comment: 06033C104JAT2A)
C46  ValueDisplayed: 0.47µF  [0603]  (hidden comment: GRM188R71E474KA12J)
C47  ValueDisplayed: 0.47µF  [0603]  (hidden comment: GRM188R71E474KA12J)
C48  ValueDisplayed: 0.1µF  [0603]  (hidden comment: 06033C104JAT2A)
C49  ValueDisplayed: 4.7µF  [0603]  (hidden comment: 0603ZD475KAT2A)
C50  ValueDisplayed: 4.7µF  [0603]  (hidden comment: 0603ZD475KAT2A)
C51  ValueDisplayed: 0.1µF  [0603]  (hidden comment: 06033C104JAT2A)
C52  ValueDisplayed: 0.1µF  [0603]  (hidden comment: 06033C104JAT2A)
C54  ValueDisplayed: 0.1µF  [0603]  (hidden comment: 06033C104JAT2A)
C55  ValueDisplayed: 4.7µF  [0603]  (hidden comment: 0603ZD475KAT2A)
C56  ValueDisplayed: 4.7µF  [0603]  (hidden comment: 0603ZD475KAT2A)
C57  ValueDisplayed: 0.1µF  [0603]  (hidden comment: 06033C104JAT2A)
D1  TLHR6405  value RED  [LED_5MM]
D2  TLHR6405  value RED  [LED_5MM]
J5  68001-403HLF  [HDR1X3]
J8  N2514-6002-RB  [3M_N2514-6002-RB]
Q1  CSD17571Q2  value 30V  [SON_CSD17571Q2]
Q2  CSD17571Q2  value 30V  [SON_CSD17571Q2]
R1  value 2.2k  [0603]  (hidden comment: CRCW06032K20JNEA)
R2  value 2.2k  [0603]  (hidden comment: CRCW06032K20JNEA)
R3  value 300  [0603]  (hidden comment: CRCW0603300RJNEA)
R4  value 300  [0603]  (hidden comment: CRCW0603300RJNEA)
R5  value 10k  [0603]  (hidden comment: CRCW060310K0JNEA)
R8  value 10k  [0603]  (hidden comment: CRCW060310K0JNEA)
R13  value 10k  [0603]  (hidden comment: CRCW060310K0JNEA)
R17  value 10k  [0603]  (hidden comment: CRCW060310K0JNEA)
R21  value 47k  [0603]  (hidden comment: CRCW060347K0JNEA)
R71  value 0  [0805_HV]  (hidden comment: CRCW08050000Z0EA)
R72  value 10  [0805_HV]  (hidden comment: CRCW080510R0JNEA)
S1  7914G-1-000E  [SW_7914G-1-000E]
TP14  TP-040_RND  [TP_25MIL-SMT]  (value not drawn)
TP15  TP-040_RND  [TP_25MIL-SMT]  (value not drawn)

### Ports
Active_LED (in), AUXVCC1, AUXVCC2, AUXVCC3, Calib_LED (in), DVCC, RESET, TCK, TDI (out), TDO, TEST/SBWTCK, TMS, VCORE, VDSYS1, VREF

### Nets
12V: R1.2 R2.2
AGND: C50.2 C51.2 C52.2 C54.2 C55.2 C56.2 C57.2 R71.1
AVCC: C54.1 C55.1 R72.2
DGND: C3.2 C4.2 C14.1 C39.2 C40.2 C41.2 C42.2 C43.2 C44.2 C45.2 C46.2 C47.2 C48.2 C49.2 J8.9 Q1.4(S) Q1.7(S) Q2.4(S) Q2.7(S) R71.2 S1.3 S1.4
DVCC: C44.1 C45.1 J5.2 R5.1 R8.1 R13.1 R17.1 R21.2 R72.1 ; port DVCC
VASYS1: C50.1 C51.1 C56.1 C57.1
Active_LED: R4.1 ; port Active_LED
AUXVCC1: C41.1 C43.1 TP15.1 ; port AUXVCC1
AUXVCC2: C40.1 C42.1 ; port AUXVCC2
AUXVCC3: C47.1 C48.1 TP14.1 ; port AUXVCC3
Calib_LED: R3.1 ; port Calib_LED
EXT: J5.3 J8.4
INT: J5.1 J8.2
RESET: C14.2 J8.11 R21.1 S1.1 S1.2 ; port RESET
TCK: J8.7 R17.2 ; port TCK
TDI: J8.3 R8.2 ; port TDI
TDO: J8.1 R5.2 ; port TDO
TEST/SBWTCK: J8.8 ; port TEST/SBWTCK
TMS: J8.5 R13.2 ; port TMS
VCORE: C46.1 ; port VCORE
VDSYS1: C39.1 C49.1 ; port VDSYS1
VREF: C52.1 ; port VREF
NetC3_1: C3.1 Q1.3(G) R3.2
NetC4_1: C4.1 Q2.3(G) R4.2
NetD1_1: D1.1(K) Q1.1(D) Q1.2(D) Q1.5(D) Q1.6(D) Q1.8(D)
NetD1_2: D1.2(A) R2.1
NetD2_1: D2.1(K) Q2.1(D) Q2.2(D) Q2.5(D) Q2.6(D) Q2.8(D)
NetD2_2: D2.2(A) R1.1

Not connected (* = marked no-connect by the designer): J8 6* 10 12 13* 14

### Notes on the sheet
- “Any unused auxiliary supply inputs (AUXVCC1, AUXVCC2, or AUXVCC3) must be
- connected to DVSS. If AUXVCC1 or AUXVCC2 are unused, their usage
- should be disabled by setting AUXxMD = 1 and AUXxOK = 0 in software, too.”

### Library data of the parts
C3 C4 C14 C39 C40 C43 C45 C48 C51 C52 C54 C57 = 06033C104JAT2A: as C10 on sheet Pg4.Analog Front End Opamp (Voltage) + LDO + ZCD
C41 C42 = 0603ZD475KAT2A: RES 0.0 OHM 1/10W JUMP 0603 SMD; Manufacturer: Vishay-Dale; CompType: Capacitor; U/M: EA; Cap_F: 0.0000047; Value1: Unknown; TaMin_C: -55; TaMax_C: 85
C44 C49 C50 C55 C56 = 0603ZD475KAT2A: CAP, CERM, 4.7uF, 10V, +/-10%, X5R, 0603; Manufacturer: AVX; Polarized: N; CompType: Capacitor; U/M: EA; Cap_F: 0.0000047; Tolerance_%: 10; Value1: Unknown; TaMin_C: -55; TaMax_C: 85
C46 C47 = GRM188R71E474KA12D: CAP, CERM, 0.47uF, 25V, +/-10%, X7R, 0603; Manufacturer: MuRata; Polarized: N; CompType: Capacitor; U/M: EA; Cap_F: 0.00000047; Tolerance_%: 10; Value1: Unknown; VDC_V: 25; TaMin_C: -55; TaMax_C: 125
D1 D2 = TLHR6405: LED, 5MM, RED, TH; Manufacturer: VISHAY; SymbolCreator: x0199378
J5 = 009155003301006: 3 pin berger; Manufacturer: FCI; SymbolCreator: a0799628; CompType: Connector; U/M: EA
J8 = 0015912140: Header, 7x2, 100mil, SMT; Manufacturer: Molex; SymbolCreator: a0412235; U/M: EA
Q1 Q2 = CSD17571Q2: MOSFET, N-CH, 30V, 22A, SON 2X2 MM; Manufacturer: TEXAS INSTRUMENTS; CompType: POWER MOSFET
R1 R2 = CRCW06032K20JNEA: RES, 2.2k ohm, 5%, 0.1W, 0603; Manufacturer: Vishay-Dale; CompType: Resistor; Res_ohm: 2200; Value_Code: 2k20; Tolerance_%: 5; Power_W: 0.1; VDC_V: 75; TempCo: 200 ppm/C; EIA_Code: E24; U/M: EA
R3 R4 = CRCW0603300RJNEA: as R16 on sheet Pg4.Analog Front End Opamp (Voltage) + LDO + ZCD
R5 R8 R13 R17 = RNCF0603TKY10K0: as R23 on sheet Pg4.Analog Front End Opamp (Voltage) + LDO + ZCD
R21 = CRCW060347K0JNEA: RES, 47k ohm, 5%, 0.1W, 0603; Manufacturer: Vishay-Dale; CompType: Resistor; Res_ohm: 47000; Value_Code: 47k0; Tolerance_%: 5; Power_W: 0.1; VDC_V: 75; TempCo: 200 ppm/C; EIA_Code: E24; U/M: EA
R71 = CRCW0805330KJNEA: as R41 on sheet Pg3.Analog Front End (Current)
R72 = CRCW080510R0JNEA: RES, 10 ohm, 5%, 0.125W, 0805; Manufacturer: Vishay-Dale; CompType: Resistor; Value_Code: 10R0; Tolerance_%: 5; Power_W: 0.125; VDC_V: 150; TempCo: 200 ppm/C; EIA_Code: E24; U/M: EA
S1 = 7914G-1-000E: Switch, Tactile, SPST-NO, 0.1A, 16V, SMT; Manufacturer: Bourns; SymbolCreator: a0412235; VDC_V: 16; SwitchFunction: Off-Mom; PositionCount: 1; CurrentRating_mA: 100
TP14 TP15 = TP-040_RND: as TP3 on sheet Pg4.Analog Front End Opamp (Voltage) + LDO + ZCD

## Sheet Pg6.MSP430F6779 + Crystal.SchDoc: MSP430F6779 + Crystal
size 431 x 279 mm; Date: Not shown in title block; ApprovedBy: Not shown in title block; CheckedBy: Not shown in title block; Author: Not shown in title block; CompanyName: Not shown in title block; Engineer: Not shown in title block; Organization: Not shown in title block; Address1: Not shown in title block; Address2: Not shown in title block; Address3: Not shown in title block; Address4: Not shown in title block; DocumentNumber: 6; Revision: Use project parameter SCH_Rev; SheetNumber: 6; SheetTotal: 8; PageSetup: Record=PageOptions|CenterHorizontal=True|CenterVertical=True|PrintScale=1.00|XCorrection=1.00|YCorrection=1.00|PrintKind=0|BorderSize=5000000|LeftOffset=0|BottomOffset=0|Orientation=2|PaperLength=1000|PaperWidth=1000|Scale=100|PaperSource=15|PrintQuality=600|MediaType=1|DitherType=10|PaperKind=Letter|PrintScaleMode=1
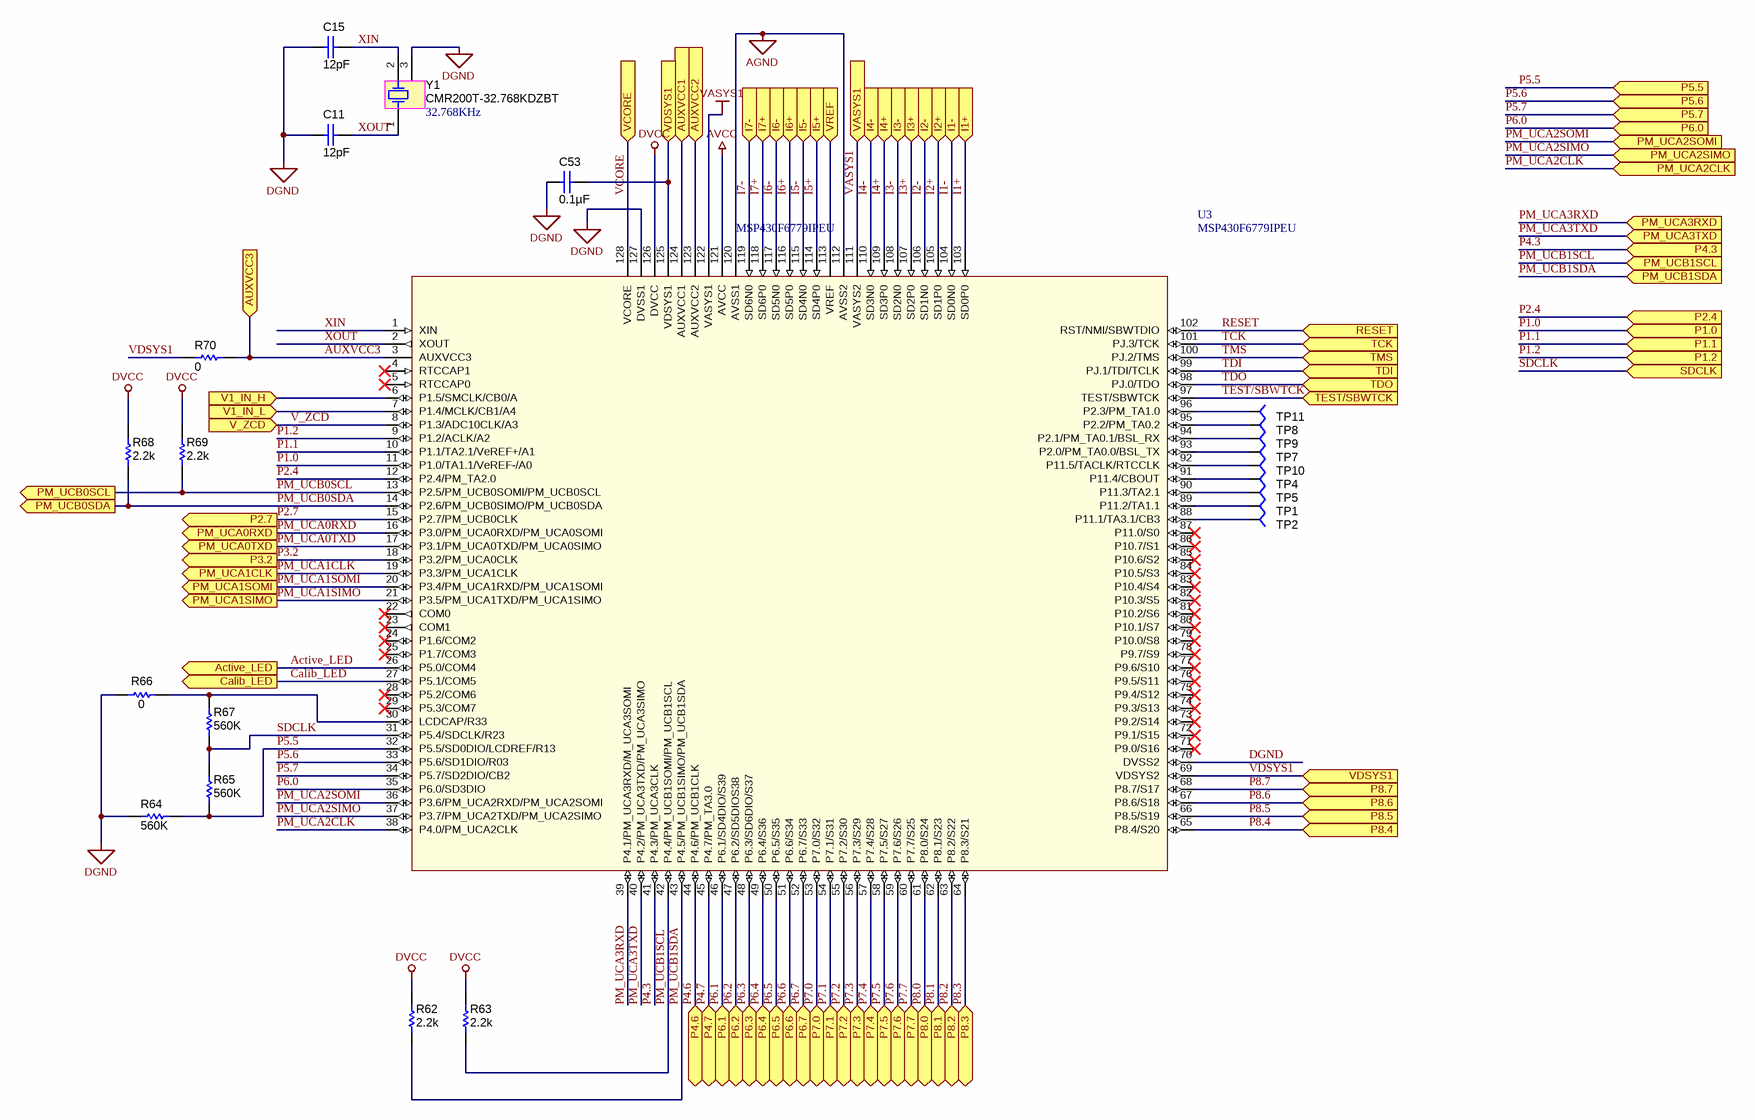
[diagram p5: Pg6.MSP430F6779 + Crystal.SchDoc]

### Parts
C11  ValueDisplayed: 12pF  [0603]  (hidden comment: 06035A120JAT2A)
C15  ValueDisplayed: 12pF  [0603]  (hidden comment: 06035A120JAT2A)
C53  ValueDisplayed: 0.1µF  [0603]  (hidden comment: 06033C104JAT2A)
R62  value 2.2k  [0603]  (hidden comment: CRCW06032K20JNEA)
R63  value 2.2k  [0603]  (hidden comment: CRCW06032K20JNEA)
R64  value 560K  [0603]  (hidden comment: CRCW0603560KFKEA)
R65  value 560K  [0603]  (hidden comment: CRCW0603560KFKEA)
R66  value 0  [0603]  (hidden comment: CRCW06030000Z0EA)
R67  value 560K  [0603]  (hidden comment: CRCW0603560KFKEA)
R68  value 2.2k  [0603]  (hidden comment: CRCW06032K20JNEA)
R69  value 2.2k  [0603]  (hidden comment: CRCW06032K20JNEA)
R70  value 0  [0805_HV]  (hidden comment: CRCW08050000Z0EA)
TP1  TP-040_RND  [TP_25MIL-SMT]  (value not drawn)
TP2  TP-040_RND  [TP_25MIL-SMT]  (value not drawn)
TP4  TP-040_RND  [TP_25MIL-SMT]  (value not drawn)
TP5  TP-040_RND  [TP_25MIL-SMT]  (value not drawn)
TP7  TP-040_RND  [TP_25MIL-SMT]  (value not drawn)
TP8  TP-040_RND  [TP_25MIL-SMT]  (value not drawn)
TP9  TP-040_RND  [TP_25MIL-SMT]  (value not drawn)
TP10  TP-040_RND  [TP_25MIL-SMT]  (value not drawn)
TP11  TP-040_RND  [TP_25MIL-SMT]  (value not drawn)
U3  MSP430F6779IPEU  [QFP50P1600X2200X160-128N]
Y1  CMR200T-32.768KDZBT  Frequency: 32.768KHz  [XTAL_CMR200T]

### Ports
Active_LED (out), AUXVCC1 (in), AUXVCC2 (in), AUXVCC3 (in), Calib_LED (out), I1+ (in), I1- (in), I2+ (in), I2- (in), I3+ (in), I3- (in), I4+ (in), I4- (in), I5+ (in), I5- (in), I6+ (in), I6- (in), I7+ (in), I7- (in), P1.0 (in), P1.1 (in), P1.2 (in), P2.4 (in), P2.7 (out), P3.2 (out), P4.3 (in), P4.6, P4.7, P5.5 (in), P5.6 (in), P5.7 (in), P6.0 (in), P6.1, P6.2, P6.3, P6.4, P6.5, P6.6, P6.7, P7.0, P7.1, P7.2, P7.3, P7.4, P7.5, P7.6, P7.7, P8.0, P8.1, P8.2, P8.3, P8.4 (in), P8.5 (in), P8.6 (in), P8.7 (in), PM_UCA0RXD (out), PM_UCA0TXD (out), PM_UCA1CLK (out), PM_UCA1SIMO (out), PM_UCA1SOMI (out), PM_UCA2CLK (in), PM_UCA2SIMO (in), PM_UCA2SOMI (in), PM_UCA3RXD (in), PM_UCA3TXD (in), PM_UCB0SCL (out), PM_UCB0SDA (out), PM_UCB1SCL (in), PM_UCB1SDA (in), RESET (in), SDCLK (in), TCK (in), TDI (in), TDO (in), TEST/SBWTCK (in), TMS (in), V1_IN_H (in), V1_IN_L (in), V_ZCD (in), VASYS1 (in), VCORE (in), VDSYS1 (in), VREF (in)

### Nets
AGND: U3.112(AVSS2) U3.120(AVSS1)
AVCC: U3.121(AVCC)
DGND: C11.2 C15.2 C53.1 R64.2 R66.1 U3.70(DVSS2) U3.127(DVSS1) Y1.3
DVCC: R62.2 R63.2 R68.2 R69.2 U3.126(DVCC)
VASYS1: U3.111(VASYS2) U3.122(VASYS1) ; port VASYS1
Active_LED: U3.26(P5.0/COM4) ; port Active_LED
AUXVCC1: U3.124(AUXVCC1) ; port AUXVCC1
AUXVCC2: U3.123(AUXVCC2) ; port AUXVCC2
AUXVCC3: R70.2 U3.3(AUXVCC3) ; port AUXVCC3
Calib_LED: U3.27(P5.1/COM5) ; port Calib_LED
I1+: U3.103(SD0P0) ; port I1+
I1-: U3.104(SD0N0) ; port I1-
I2+: U3.105(SD1P0) ; port I2+
I2-: U3.106(SD1N0) ; port I2-
I3+: U3.107(SD2P0) ; port I3+
I3-: U3.108(SD2N0) ; port I3-
I4+: U3.109(SD3P0) ; port I4+
I4-: U3.110(SD3N0) ; port I4-
I5+: U3.114(SD4P0) ; port I5+
I5-: U3.115(SD4N0) ; port I5-
I6+: U3.116(SD5P0) ; port I6+
I6-: U3.117(SD5N0) ; port I6-
I7+: U3.118(SD6P0) ; port I7+
I7-: U3.119(SD6N0) ; port I7-
P1.0: U3.11(P1.0/TA1.1/VeREF-/A0) ; port P1.0
P1.1: U3.10(P1.1/TA2.1/VeREF+/A1) ; port P1.1
P1.2: U3.9(P1.2/ACLK/A2) ; port P1.2
P2.4: U3.12(P2.4/PM_TA2.0) ; port P2.4
P2.7: U3.15(P2.7/PM_UCB0CLK) ; port P2.7
P3.2: U3.18(P3.2/PM_UCA0CLK) ; port P3.2
P4.3: U3.41(P4.3/PM_UCA3CLK) ; port P4.3
P4.6: U3.44(P4.6/PM_UCB1CLK) ; port P4.6
P4.7: U3.45(P4.7/PM_TA3.0) ; port P4.7
P5.5: R64.1 R65.1 U3.32(P5.5/SD0DIO/LCDREF/R13) ; port P5.5
P5.6: U3.33(P5.6/SD1DIO/R03) ; port P5.6
P5.7: U3.34(P5.7/SD2DIO/CB2) ; port P5.7
P6.0: U3.35(P6.0/SD3DIO) ; port P6.0
P6.1: U3.46(P6.1/SD4DIO/S39) ; port P6.1
P6.2: U3.47(P6.2/SD5DIOS38) ; port P6.2
P6.3: U3.48(P6.3/SD6DIO/S37) ; port P6.3
P6.4: U3.49(P6.4/S36) ; port P6.4
P6.5: U3.50(P6.5/S35) ; port P6.5
P6.6: U3.51(P6.6/S34) ; port P6.6
P6.7: U3.52(P6.7/S33) ; port P6.7
P7.0: U3.53(P7.0/S32) ; port P7.0
P7.1: U3.54(P7.1/S31) ; port P7.1
P7.2: U3.55(P7.2/S30) ; port P7.2
P7.3: U3.56(P7.3/S29) ; port P7.3
P7.4: U3.57(P7.4/S28) ; port P7.4
P7.5: U3.58(P7.5/S27) ; port P7.5
P7.6: U3.59(P7.6/S26) ; port P7.6
P7.7: U3.60(P7.7/S25) ; port P7.7
P8.0: U3.61(P8.0/S24) ; port P8.0
P8.1: U3.62(P8.1/S23) ; port P8.1
P8.2: U3.63(P8.2/S22) ; port P8.2
P8.3: U3.64(P8.3/S21) ; port P8.3
P8.4: U3.65(P8.4/S20) ; port P8.4
P8.5: U3.66(P8.5/S19) ; port P8.5
P8.6: U3.67(P8.6/S18) ; port P8.6
P8.7: U3.68(P8.7/S17) ; port P8.7
PM_UCA0RXD: U3.16(P3.0/PM_UCA0RXD/PM_UCA0SOMI) ; port PM_UCA0RXD
PM_UCA0TXD: U3.17(P3.1/PM_UCA0TXD/PM_UCA0SIMO) ; port PM_UCA0TXD
PM_UCA1CLK: U3.19(P3.3/PM_UCA1CLK) ; port PM_UCA1CLK
PM_UCA1SIMO: U3.21(P3.5/PM_UCA1TXD/PM_UCA1SIMO) ; port PM_UCA1SIMO
PM_UCA1SOMI: U3.20(P3.4/PM_UCA1RXD/PM_UCA1SOMI) ; port PM_UCA1SOMI
PM_UCA2CLK: U3.38(P4.0/PM_UCA2CLK) ; port PM_UCA2CLK
PM_UCA2SIMO: U3.37(P3.7/PM_UCA2TXD/PM_UCA2SIMO) ; port PM_UCA2SIMO
PM_UCA2SOMI: U3.36(P3.6/PM_UCA2RXD/PM_UCA2SOMI) ; port PM_UCA2SOMI
PM_UCA3RXD: U3.39(P4.1/PM_UCA3RXD/M_UCA3SOMI) ; port PM_UCA3RXD
PM_UCA3TXD: U3.40(P4.2/PM_UCA3TXD/PM_UCA3SIMO) ; port PM_UCA3TXD
PM_UCB0SCL: R69.1 U3.13(P2.5/PM_UCB0SOMI/PM_UCB0SCL) ; port PM_UCB0SCL
PM_UCB0SDA: R68.1 U3.14(P2.6/PM_UCB0SIMO/PM_UCB0SDA) ; port PM_UCB0SDA
PM_UCB1SCL: R63.1 U3.42(P4.4/PM_UCB1SOMI/PM_UCB1SCL) ; port PM_UCB1SCL
PM_UCB1SDA: R62.1 U3.43(P4.5/PM_UCB1SIMO/PM_UCB1SDA) ; port PM_UCB1SDA
RESET: U3.102(RST/NMI/SBWTDIO) ; port RESET
SDCLK: R65.2 R67.1 U3.31(P5.4/SDCLK/R23) ; port SDCLK
TCK: U3.101(PJ.3/TCK) ; port TCK
TDI: U3.99(PJ.1/TDI/TCLK) ; port TDI
TDO: U3.98(PJ.0/TDO) ; port TDO
TEST/SBWTCK: U3.97(TEST/SBWTCK) ; port TEST/SBWTCK
TMS: U3.100(PJ.2/TMS) ; port TMS
V1_IN_H: U3.6(P1.5/SMCLK/CB0/A) ; port V1_IN_H
V1_IN_L: U3.7(P1.4/MCLK/CB1/A4) ; port V1_IN_L
V_ZCD: U3.8(P1.3/ADC10CLK/A3) ; port V_ZCD
VCORE: U3.128(VCORE) ; port VCORE
VDSYS1: C53.2 R70.1 U3.69(VDSYS2) U3.125(VDSYS1) ; port VDSYS1
VREF: U3.113(VREF) ; port VREF
XIN: C15.1 U3.1(XIN) Y1.2
XOUT: C11.1 U3.2(XOUT) Y1.1
NetR66_2: R66.2 R67.2 U3.30(LCDCAP/R33)
NetTP1_1: TP1.1 U3.89(P11.2/TA1.1)
NetTP2_1: TP2.1 U3.88(P11.1/TA3.1/CB3)
NetTP4_1: TP4.1 U3.91(P11.4/CBOUT)
NetTP5_1: TP5.1 U3.90(P11.3/TA2.1)
NetTP7_1: TP7.1 U3.93(P2.0/PM_TA0.0/BSL_TX)
NetTP8_1: TP8.1 U3.95(P2.2/PM_TA0.2)
NetTP9_1: TP9.1 U3.94(P2.1/PM_TA0.1/BSL_RX)
NetTP10_1: TP10.1 U3.92(P11.5/TACLK/RTCCLK)
NetTP11_1: TP11.1 U3.96(P2.3/PM_TA1.0)

Not connected (* = marked no-connect by the designer): U3 4(RTCCAP1)* 5(RTCCAP0)* 22(COM0)* 23(COM1)* 24(P1.6/COM2)* 25(P1.7/COM3)* 28(P5.2/COM6)* 29(P5.3/COM7)* 71(P9.0/S16)* 72(P9.1/S15)* 73(P9.2/S14)* 74(P9.3/S13)* 75(P9.4/S12)* 76(P9.5/S11)* 77(P9.6/S10)* 78(P9.7/S9)* 79(P10.0/S8)* 80(P10.1/S7)* 81(P10.2/S6)* 82(P10.3/S5)* 83(P10.4/S4)* 84(P10.5/S3)* 85(P10.6/S2)* 86(P10.7/S1)* 87(P11.0/S0)*

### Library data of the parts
C11 C15 = 06035A120JAT2A: CAP, CERM, 12pF, 50V, +/-5%, C0G/NP0, 0603; Manufacturer: AVX; Polarized: N; CompType: Capacitor; U/M: EA; Cap_F: 0.000000000012; Tolerance_%: 5; ESR_Ohm: 0.363; Value1: 0.363 ohm; VDC_V: 50; TaMin_C: -55; TaMax_C: 125
C53 = 06033C104JAT2A: as C10 on sheet Pg4.Analog Front End Opamp (Voltage) + LDO + ZCD
R62 R63 R68 R69 = CRCW06032K20JNEA: as R1 on sheet Pg5.JTAG Interface + LEDs + Decoupling Capacitors
R64 R65 R67 = CRCW06032K20JNEA: RES 560K OHM 1/10W 1% 0603 SMD; Manufacturer: Vishay-Dale; CompType: Resistor; Tolerance_%: 1; Power_W: 0.1; Value2: 0.1W; VDC_V: 75; TempCo: 100 ppm/C; EIA_Code: E24; U/M: EA
R66 = CRCW08050000Z0EA: RES 0.0 OHM 1/10W JUMP 0603 SMD; Manufacturer: Vishay-Dale; CompType: Resistor; Value_Code: 0000; Tolerance_%: 5; Power_W: 0.125; Value2: 0.1W; VDC_V: 150; EIA_Code: E24; U/M: EA
R70 = CRCW0805330KJNEA: as R41 on sheet Pg3.Analog Front End (Current)
TP1 TP2 TP4 TP5 TP7-TP11 = TP-040_RND: as TP3 on sheet Pg4.Analog Front End Opamp (Voltage) + LDO + ZCD
U3 = MSP430F6779IPEU: IC, MCU 16BIT 512KB FLASH, LQFP-128; Manufacturer: TEXAS INSTRUMENTS; SymbolCreator: x0199378
Y1 = CMR200T-32.768KDZBT: CRYSTAL, 32.768KHz, 6PF, +/- 20PPM, SMD-3P; Manufacturer: CITIZEN; SymbolCreator: x0199378

## Sheet Pg7.Interfaces.SchDoc: Interfaces
size 431 x 279 mm; Date: Not shown in title block; ApprovedBy: Not shown in title block; CheckedBy: Not shown in title block; Author: Not shown in title block; CompanyName: Not shown in title block; Engineer: Not shown in title block; Organization: Not shown in title block; Address1: Not shown in title block; Address2: Not shown in title block; Address3: Not shown in title block; Address4: Not shown in title block; DocumentNumber: 7; Revision: Use project parameter SCH_Rev; SheetNumber: 7; SheetTotal: 8; PageSetup: Record=PageOptions|CenterHorizontal=True|CenterVertical=True|PrintScale=1.00|XCorrection=1.00|YCorrection=1.00|PrintKind=0|BorderSize=5000000|LeftOffset=0|BottomOffset=0|Orientation=2|PaperLength=1000|PaperWidth=1000|Scale=100|PaperSource=15|PrintQuality=600|MediaType=1|DitherType=10|PaperKind=Letter|PrintScaleMode=1
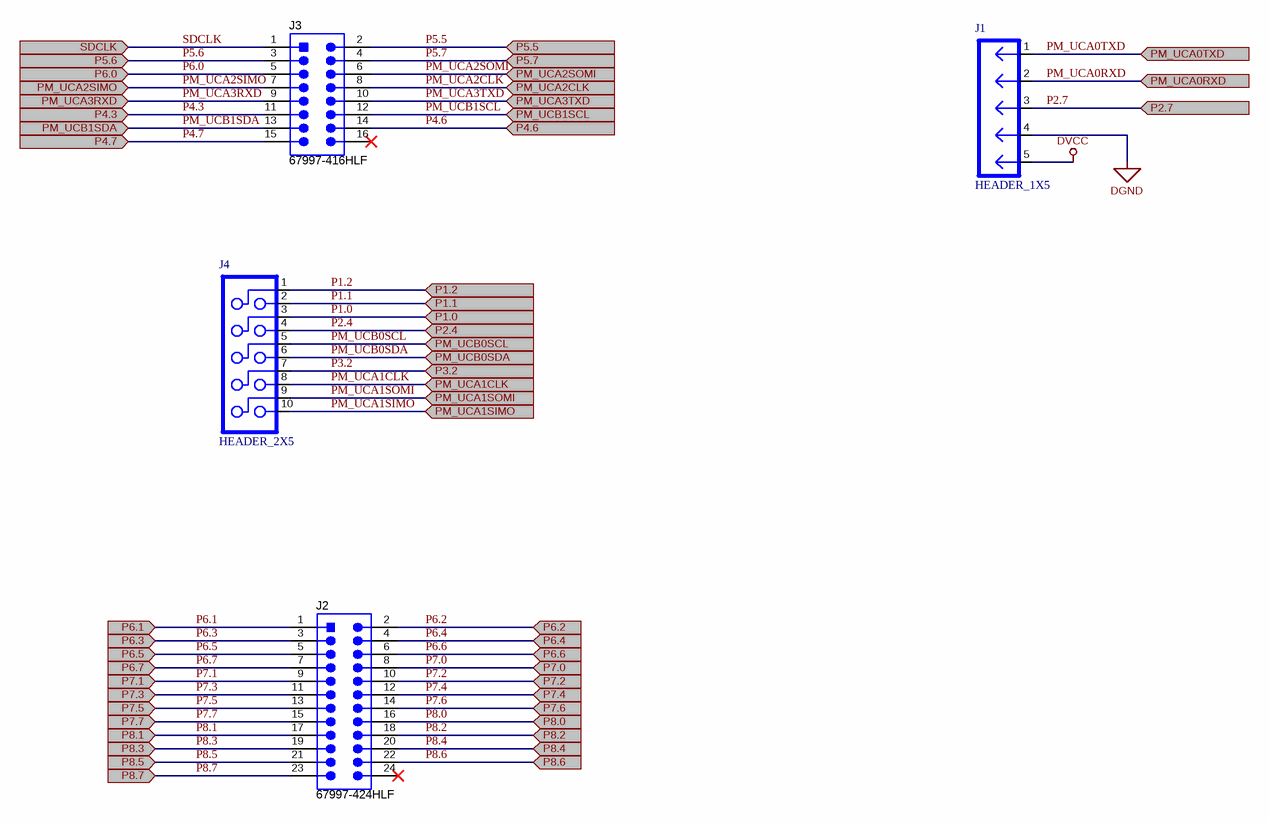
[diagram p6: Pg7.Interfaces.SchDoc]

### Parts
J1  HEADER_1X5  [HEADER_5P]
J2  67997-424HLF  [TSW-112-07-G-D]
J3  67997-416HLF  [TSW-108-07-G-D]
J4  HEADER_2X5  [HDR2X5]

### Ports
P1.0, P1.1, P1.2, P2.4, P2.7, P3.2, P4.3, P4.6, P4.7, P5.5, P5.6, P5.7, P6.0, P6.1, P6.2, P6.3, P6.4, P6.5, P6.6, P6.7, P7.0, P7.1, P7.2, P7.3, P7.4, P7.5, P7.6, P7.7, P8.0, P8.1, P8.2, P8.3, P8.4, P8.5, P8.6, P8.7, PM_UCA0RXD, PM_UCA0TXD, PM_UCA1CLK, PM_UCA1SIMO, PM_UCA1SOMI, PM_UCA2CLK, PM_UCA2SIMO, PM_UCA2SOMI, PM_UCA3RXD, PM_UCA3TXD, PM_UCB0SCL, PM_UCB0SDA, PM_UCB1SCL, PM_UCB1SDA, SDCLK

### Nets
DGND: J1.4
DVCC: J1.5
P1.0: J4.3(P3) ; port P1.0
P1.1: J4.2(P2) ; port P1.1
P1.2: J4.1(P1) ; port P1.2
P2.4: J4.4(P4) ; port P2.4
P2.7: J1.3 ; port P2.7
P3.2: J4.7(P7) ; port P3.2
P4.3: J3.11 ; port P4.3
P4.6: J3.14 ; port P4.6
P4.7: J3.15 ; port P4.7
P5.5: J3.2 ; port P5.5
P5.6: J3.3 ; port P5.6
P5.7: J3.4 ; port P5.7
P6.0: J3.5 ; port P6.0
P6.1: J2.1 ; port P6.1
P6.2: J2.2 ; port P6.2
P6.3: J2.3 ; port P6.3
P6.4: J2.4 ; port P6.4
P6.5: J2.5 ; port P6.5
P6.6: J2.6 ; port P6.6
P6.7: J2.7 ; port P6.7
P7.0: J2.8 ; port P7.0
P7.1: J2.9 ; port P7.1
P7.2: J2.10 ; port P7.2
P7.3: J2.11 ; port P7.3
P7.4: J2.12 ; port P7.4
P7.5: J2.13 ; port P7.5
P7.6: J2.14 ; port P7.6
P7.7: J2.15 ; port P7.7
P8.0: J2.16 ; port P8.0
P8.1: J2.17 ; port P8.1
P8.2: J2.18 ; port P8.2
P8.3: J2.19 ; port P8.3
P8.4: J2.20 ; port P8.4
P8.5: J2.21 ; port P8.5
P8.6: J2.22 ; port P8.6
P8.7: J2.23 ; port P8.7
PM_UCA0RXD: J1.2 ; port PM_UCA0RXD
PM_UCA0TXD: J1.1 ; port PM_UCA0TXD
PM_UCA1CLK: J4.8(P8) ; port PM_UCA1CLK
PM_UCA1SIMO: J4.10(P10) ; port PM_UCA1SIMO
PM_UCA1SOMI: J4.9(P9) ; port PM_UCA1SOMI
PM_UCA2CLK: J3.8 ; port PM_UCA2CLK
PM_UCA2SIMO: J3.7 ; port PM_UCA2SIMO
PM_UCA2SOMI: J3.6 ; port PM_UCA2SOMI
PM_UCA3RXD: J3.9 ; port PM_UCA3RXD
PM_UCA3TXD: J3.10 ; port PM_UCA3TXD
PM_UCB0SCL: J4.5(P5) ; port PM_UCB0SCL
PM_UCB0SDA: J4.6(P6) ; port PM_UCB0SDA
PM_UCB1SCL: J3.12 ; port PM_UCB1SCL
PM_UCB1SDA: J3.13 ; port PM_UCB1SDA
SDCLK: J3.1 ; port SDCLK

Not connected (* = marked no-connect by the designer): J2 24*; J3 16*

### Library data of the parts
J1 = HEADER_1X5: Header, Male 5-pin, 100mil spacing,; Manufacturer: TE Connectivity; PartNumber: 826926-5; area: 55000; Value: PEC05SAAN
J2 = TSW-112-07-G-D: Header, TH, 100mil, 12x2, Gold plated, 230 mil above insulator; Manufacturer: FCI; SymbolCreator: a0412235; U/M: EA
J3 = PBC08DBAN: Header, 8x2, 100mil, TH; Manufacturer: FCI; SymbolCreator: a0412235; U/M: EA
J4 = HEADER_2X5: Header, Male 2x5-pin, 100mil spacing; Manufacturer: FCI; PartNumber: 67997-410HLF; area: 100000; Value: PEC05DAAN

## Sheet Pg8.HARDWARE - MISCELLANEOUS.SchDoc: Hardware - MIiscellaneous
size 431 x 279 mm; Date: Not shown in title block; ApprovedBy: Not shown in title block; CheckedBy: Not shown in title block; Author: Not shown in title block; CompanyName: Not shown in title block; Engineer: Not shown in title block; Organization: Not shown in title block; Address1: Not shown in title block; Address2: Not shown in title block; Address3: Not shown in title block; Address4: Not shown in title block; DocumentNumber: 8; Revision: Use project parameter SCH_Rev; SheetNumber: 8; SheetTotal: 8; PageSetup: Record=PageOptions|CenterHorizontal=True|CenterVertical=True|PrintScale=1.00|XCorrection=1.00|YCorrection=1.00|PrintKind=0|BorderSize=5000000|LeftOffset=0|BottomOffset=0|Orientation=2|PaperLength=1000|PaperWidth=1000|Scale=100|PaperSource=15|PrintQuality=600|MediaType=1|DitherType=10|PaperKind=Letter|PrintScaleMode=1
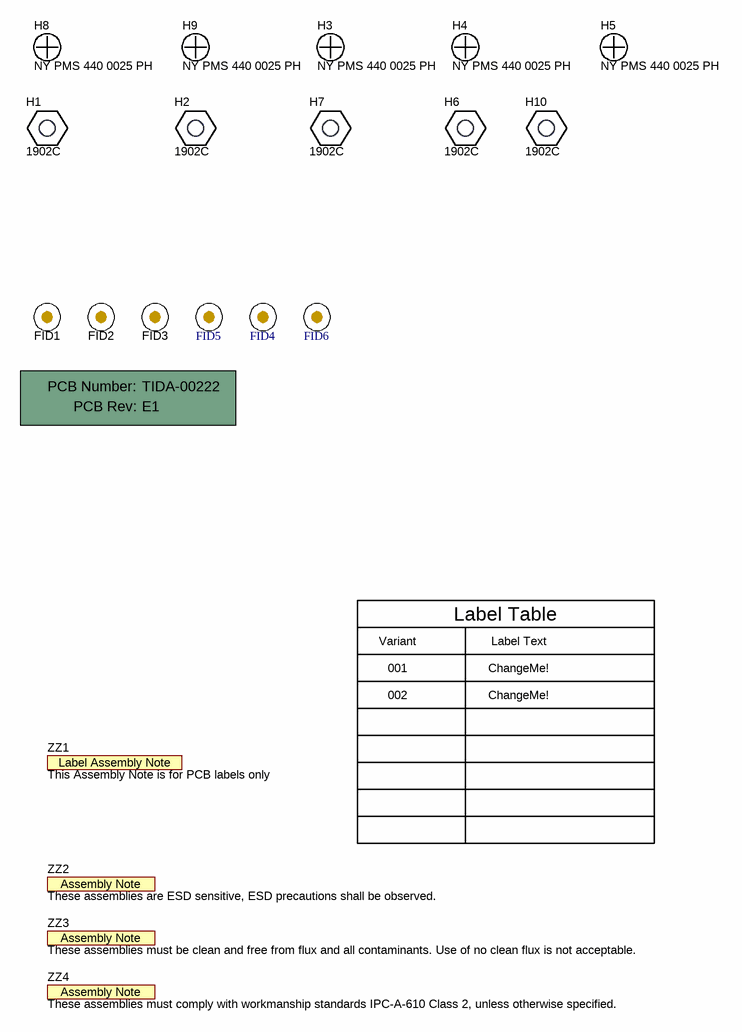
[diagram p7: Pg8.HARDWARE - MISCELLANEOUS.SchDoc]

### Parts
!PCB1  Printed Circuit Board  (value not drawn)  (mechanical)
FID1  Fiducial  [Fiducial10-20]  (value not drawn)
FID2  Fiducial  [Fiducial10-20]  (value not drawn)
FID3  Fiducial  [Fiducial10-20]  (value not drawn)
FID4  Fiducial  [Fiducial10-30]  (value not drawn)
FID5  Fiducial  [Fiducial10-30]  (value not drawn)
FID6  Fiducial  [Fiducial10-30]  (value not drawn)
H1  1902C  [Keystone_1902C]
H2  1902C  [Keystone_1902C]
H3  NY PMS 440 0025 PH  [NY PMS 440 0025 PH]
H4  NY PMS 440 0025 PH  [NY PMS 440 0025 PH]
H5  NY PMS 440 0025 PH  [NY PMS 440 0025 PH]
H6  1902C  [Keystone_1902C]
H7  1902C  [Keystone_1902C]
H8  NY PMS 440 0025 PH  [NY PMS 440 0025 PH]
H9  NY PMS 440 0025 PH  [NY PMS 440 0025 PH]
H10  1902C  [Keystone_1902C]
ZZ1  This Assembly Note is for PCB labels only  [AssemblyNoteLabel]  (no BOM)
ZZ2  These assemblies are ESD sensitive, ESD precautions shall be observed.  [AssemblyNote]  (no BOM)
ZZ3  These assemblies must be clean and free from flux and all contaminants. Use of no clean flux is not acceptable.  [AssemblyNote]  (no BOM)
ZZ4  These assemblies must comply with workmanship standards IPC-A-610 Class 2, unless otherwise specified.  [AssemblyNote]  (no BOM)

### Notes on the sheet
- Variant
- Label Table
- Label Text
- 001
- 002
- ChangeMe!

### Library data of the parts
!PCB1 = PCB: Manufacturer: Any; PartNumber: TIDA-00222; SymbolCreator: a0412235
FID1-FID6 = Fiducial: Fiducial mark.  There is nothing to buy or mount.; SymbolCreator: codlsc
H1 H2 H6 H7 H10 = 1902C: Standoff, Hex, 0.5"L #4-40 Nylon; Manufacturer: Keystone; CompType: Hardware
H3-H5 H8 H9 = NY PMS 440 0025 PH: Machine Screw, Round, #4-40 x 1/4, Nylon, Philips panhead; Manufacturer: B&F Fastener Supply; CompType: Hardware; SymbolCreator: codlsc; U/M: EA
ZZ1 = AssemblyNoteLabel: SymbolCreator: a0412235
ZZ2-ZZ4 = AssemblyNote: SymbolCreator: codlsc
